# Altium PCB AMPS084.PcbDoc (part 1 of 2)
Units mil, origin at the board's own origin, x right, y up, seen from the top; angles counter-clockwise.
Board outline 7000 x 5000 mil, 4 copper layers (Top Layer, Int 2 V-, Int 3 V+, Bottom Layer), stack 61.634 mil thick; 175 components, 69 nets, 389 pads, 136 vias.
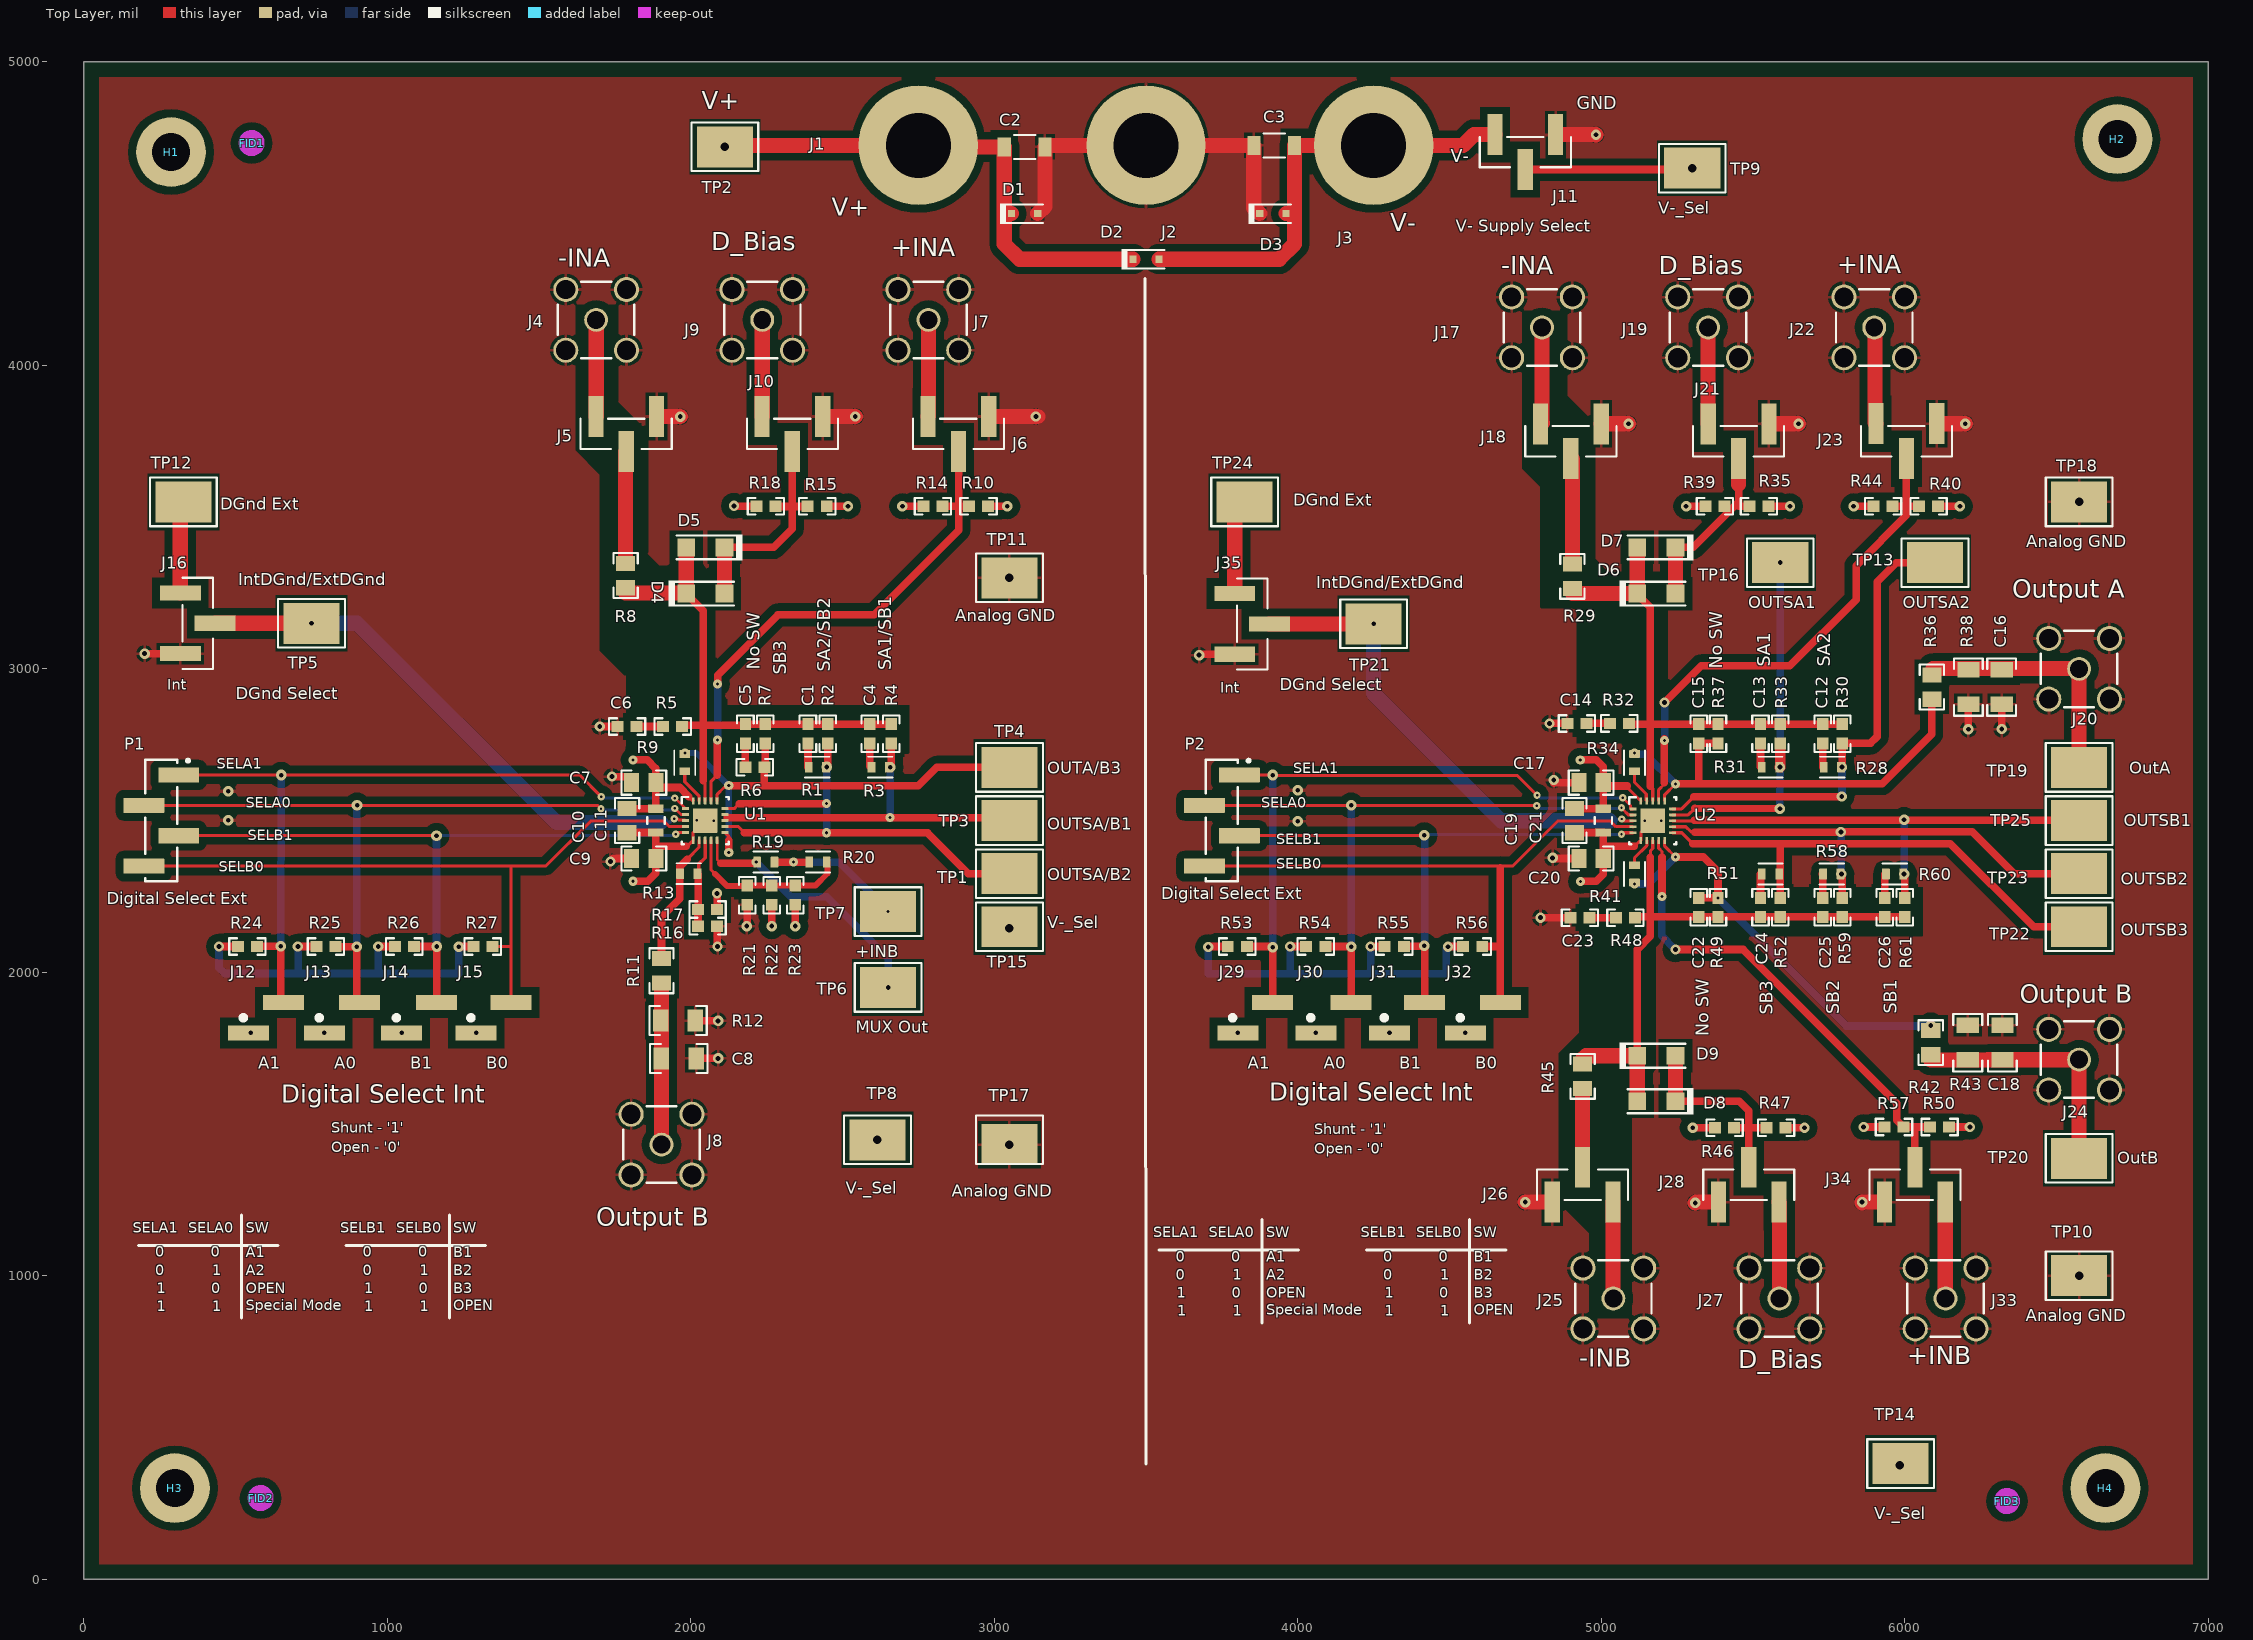
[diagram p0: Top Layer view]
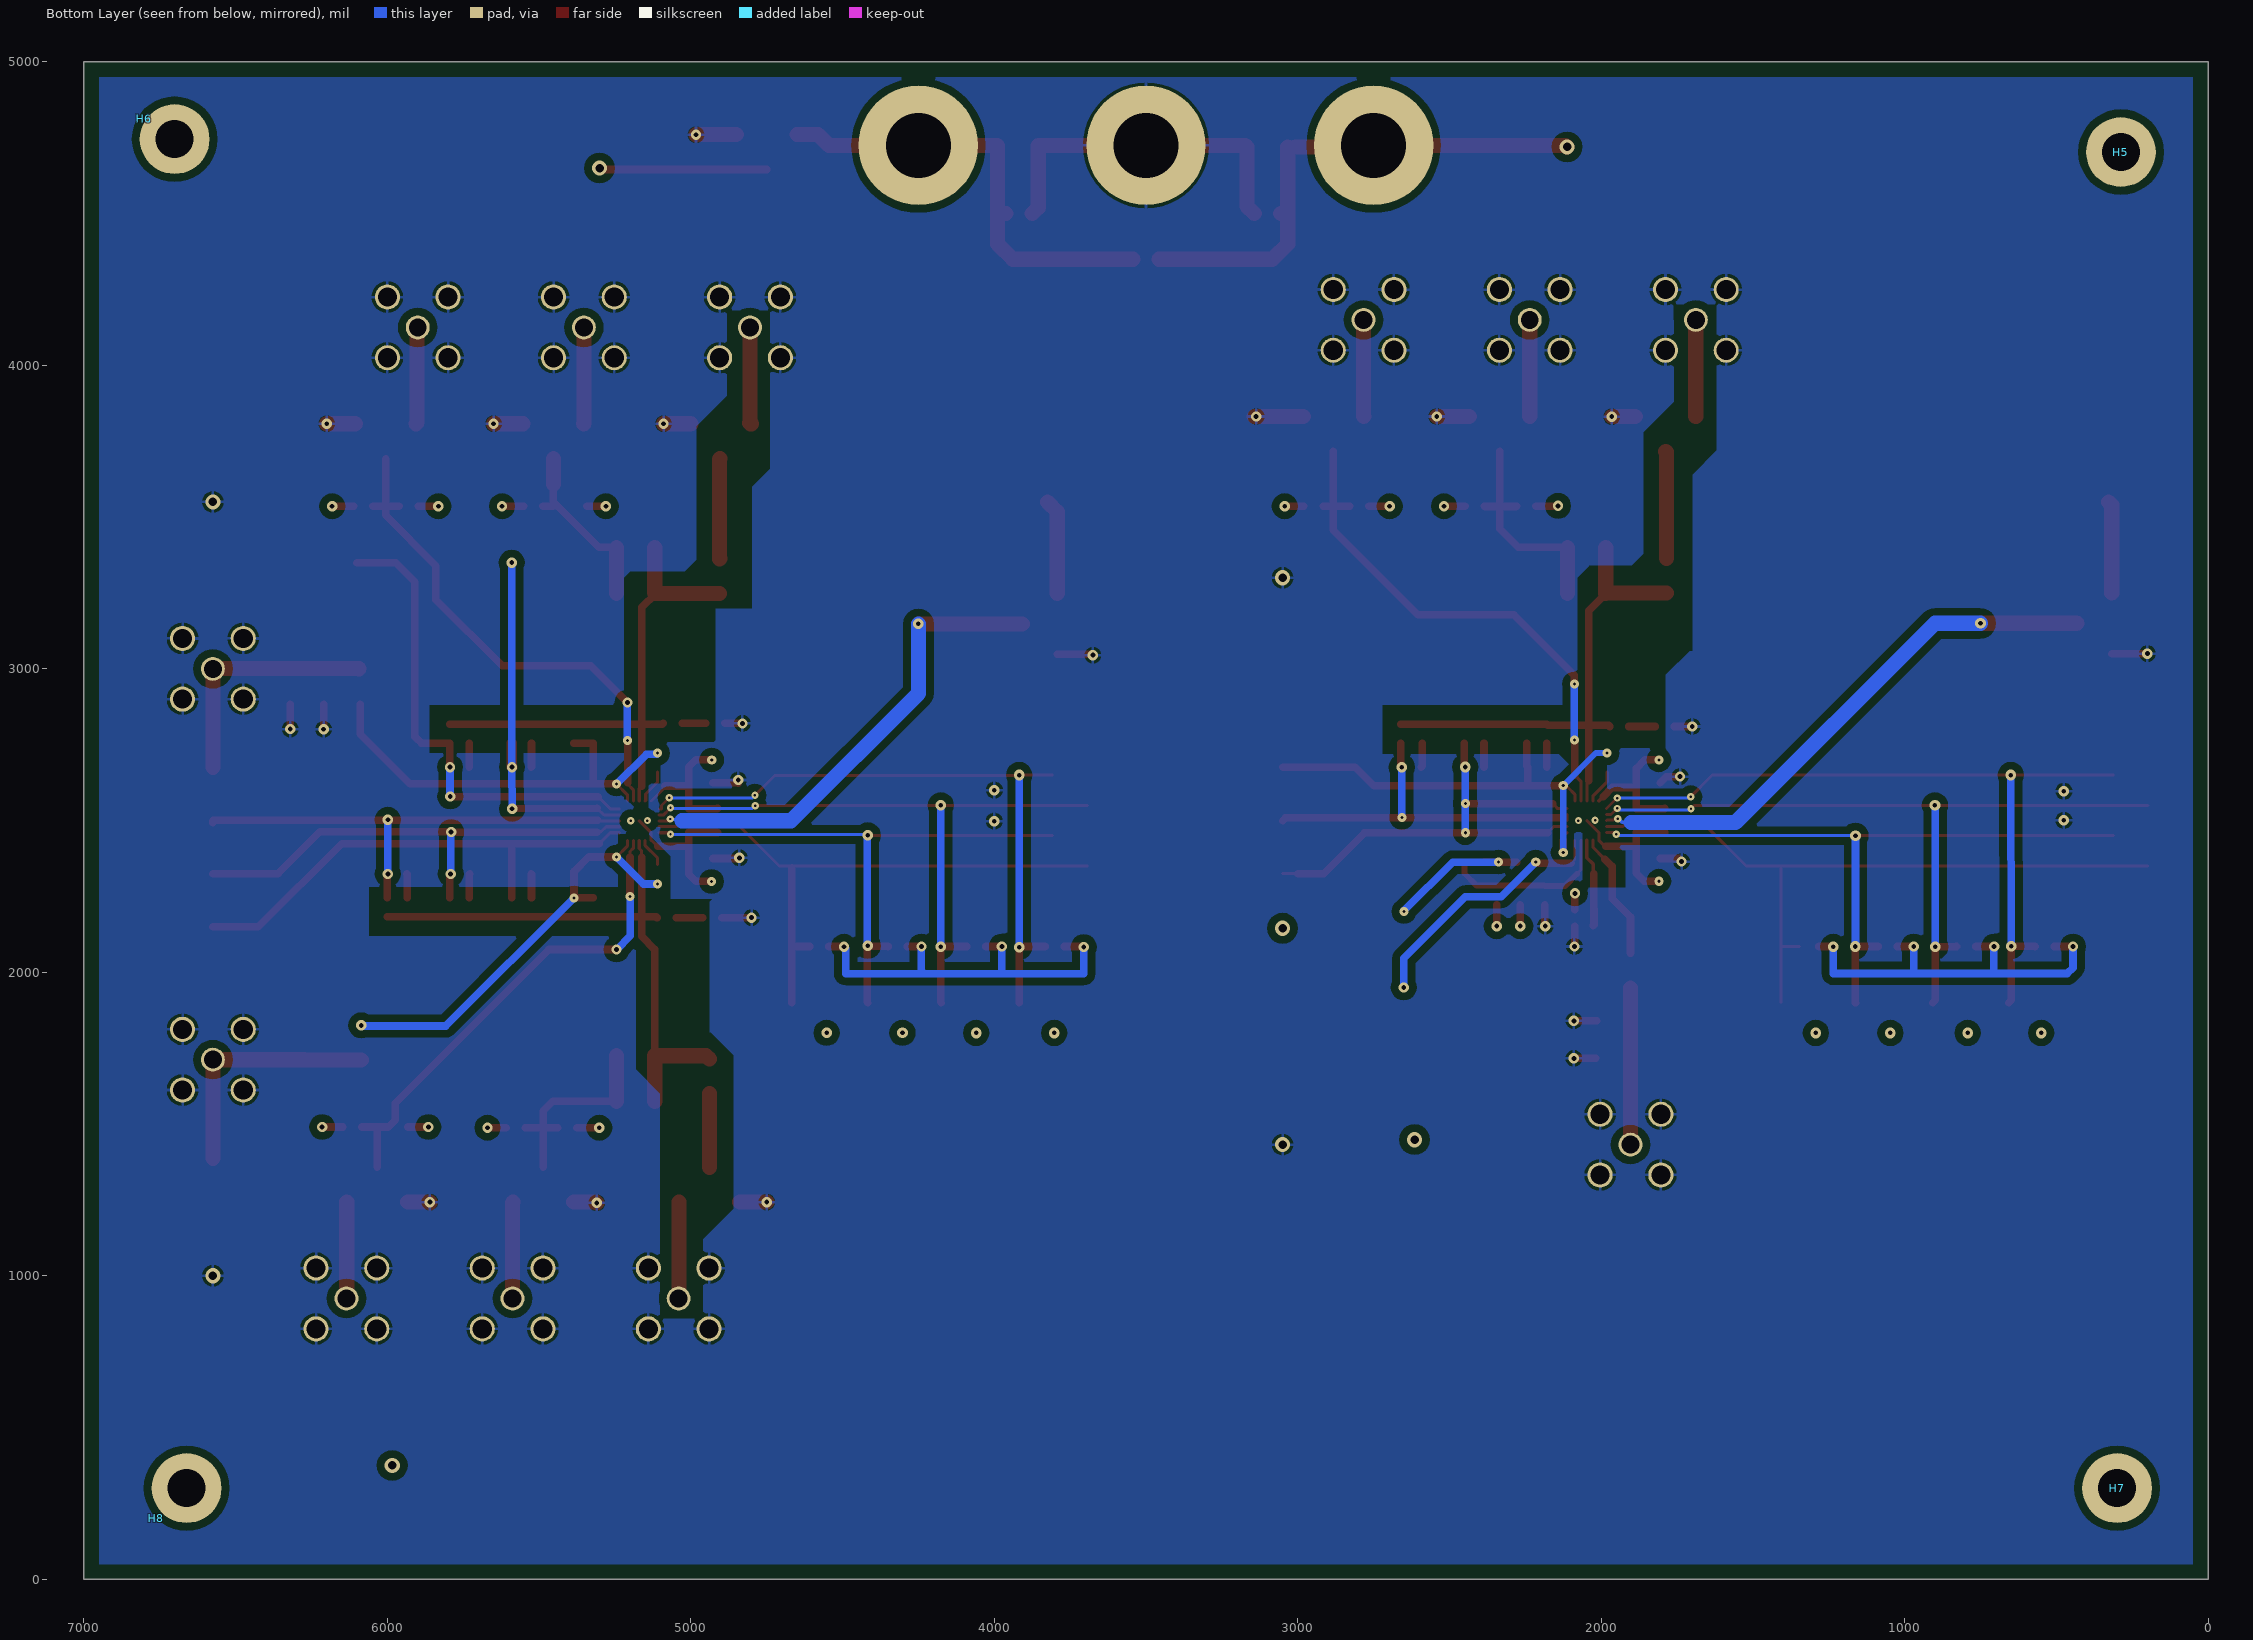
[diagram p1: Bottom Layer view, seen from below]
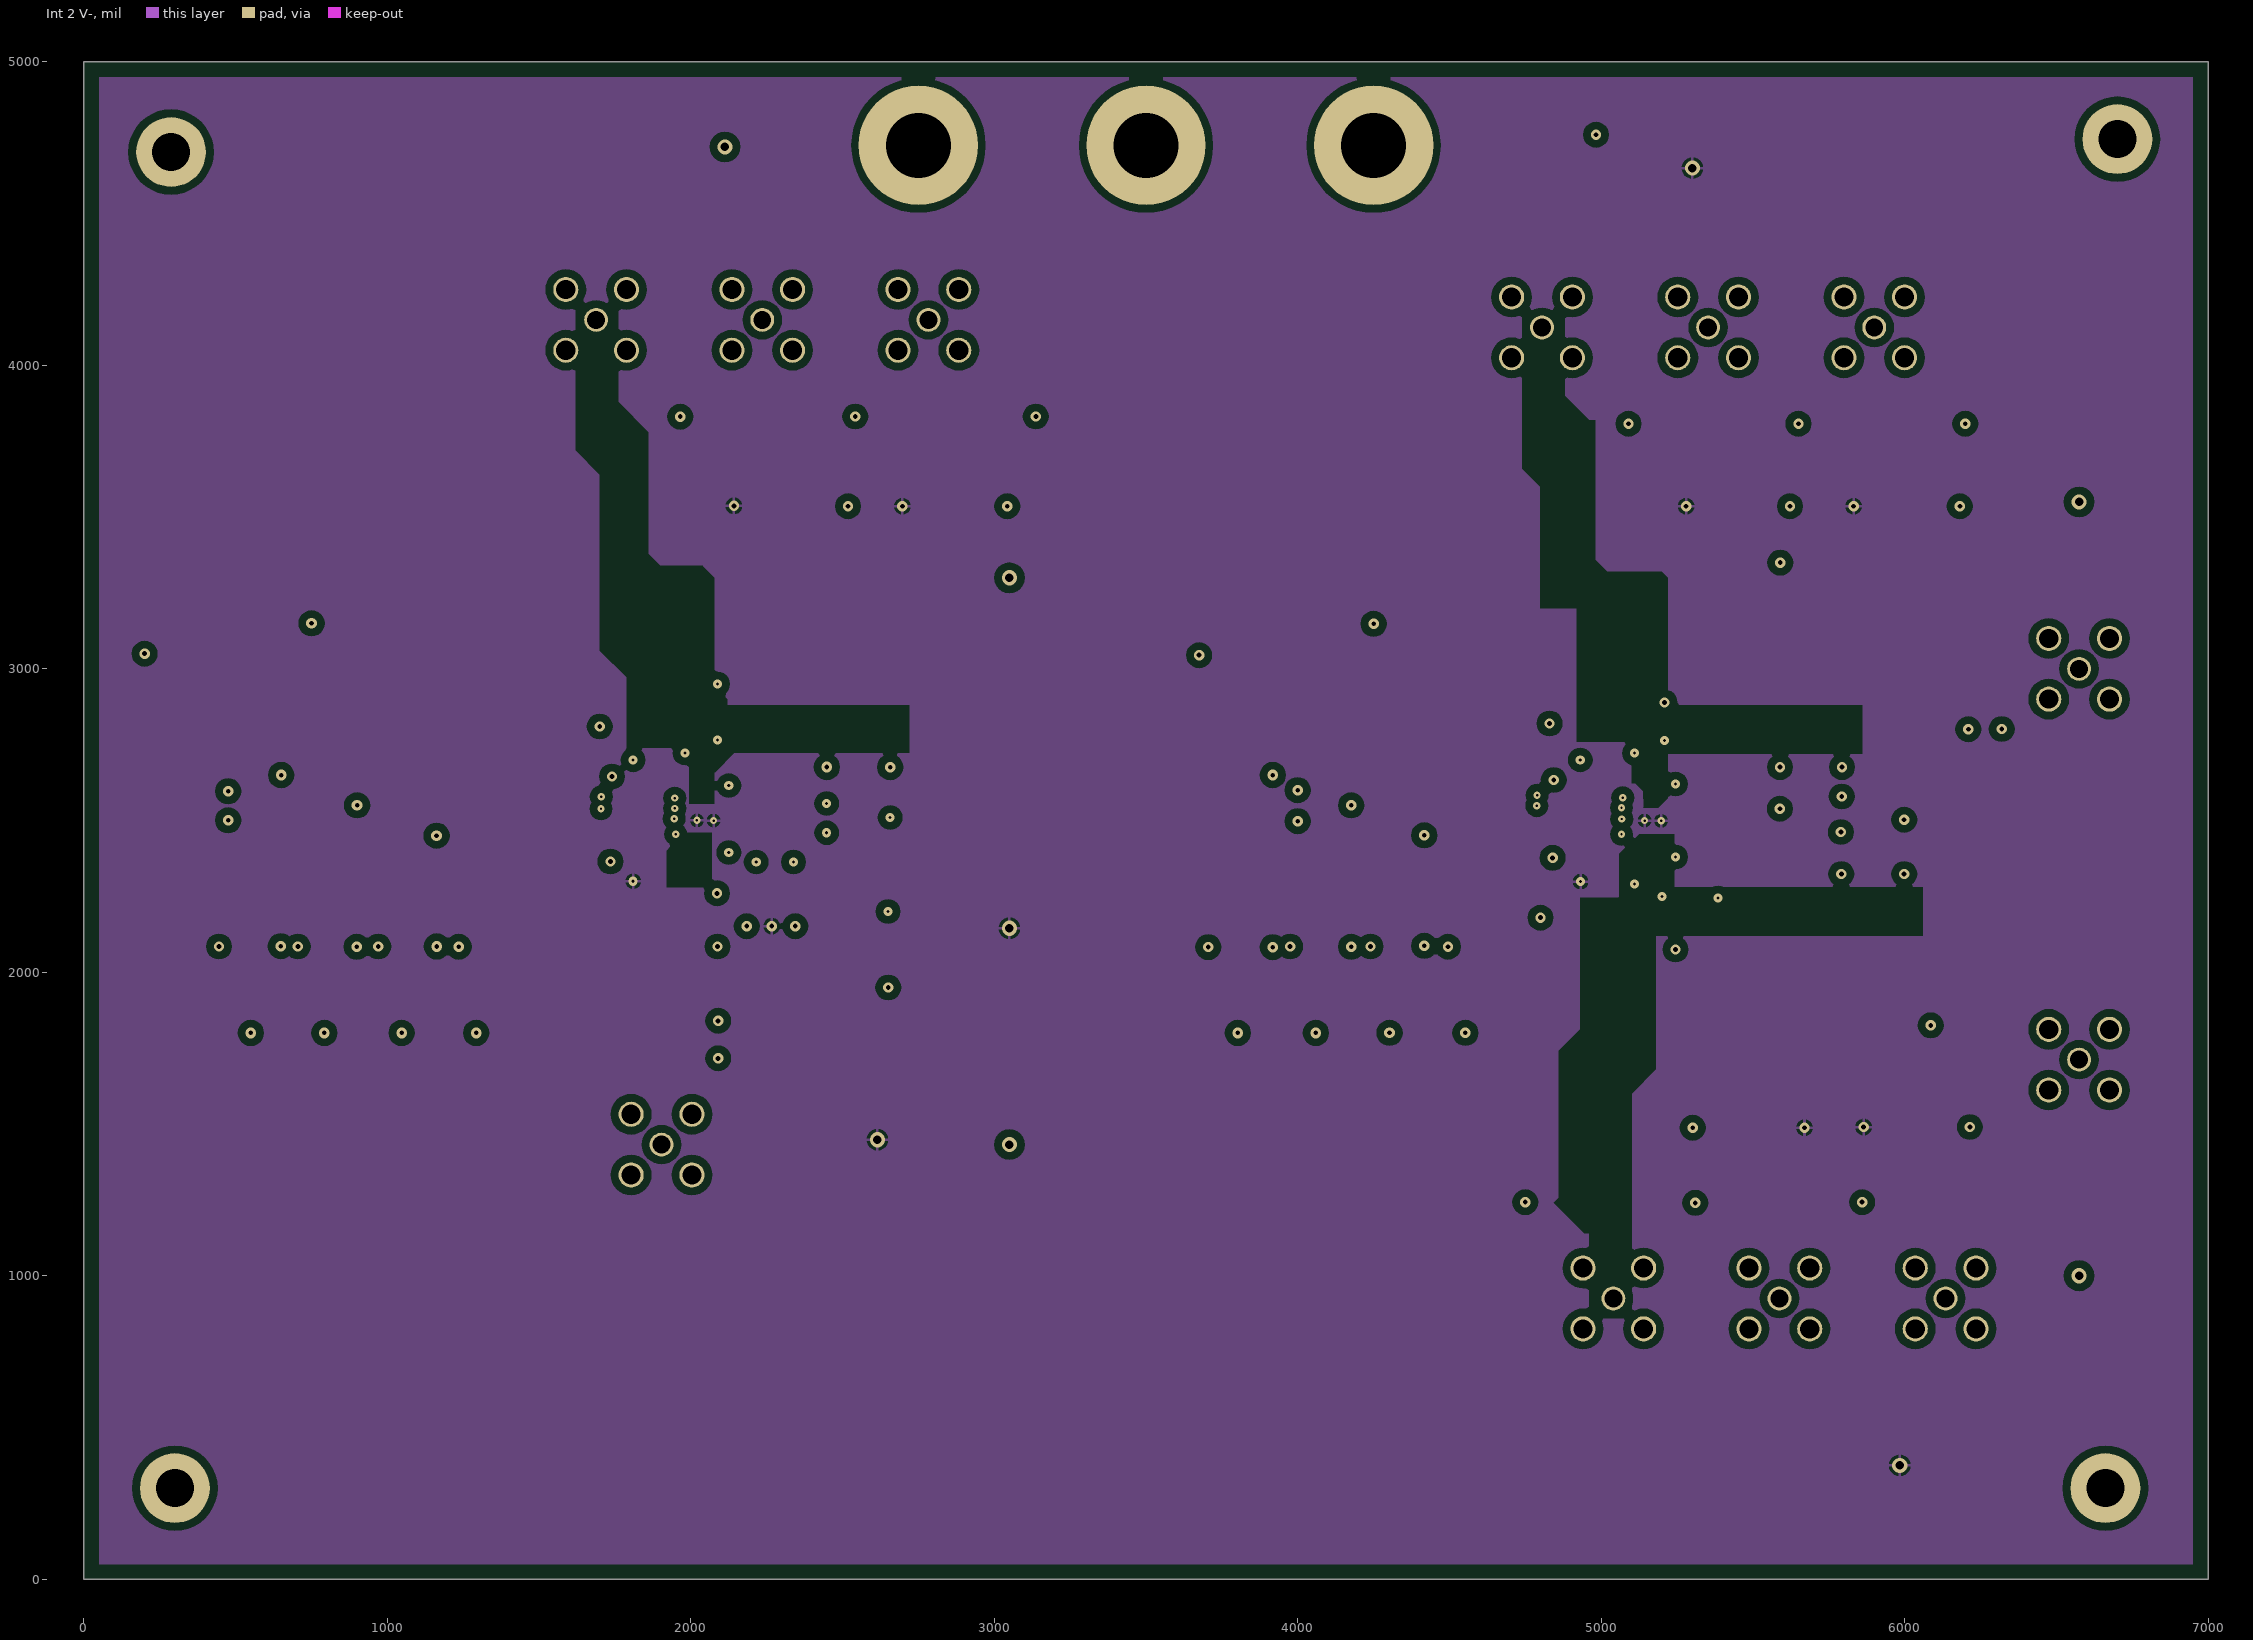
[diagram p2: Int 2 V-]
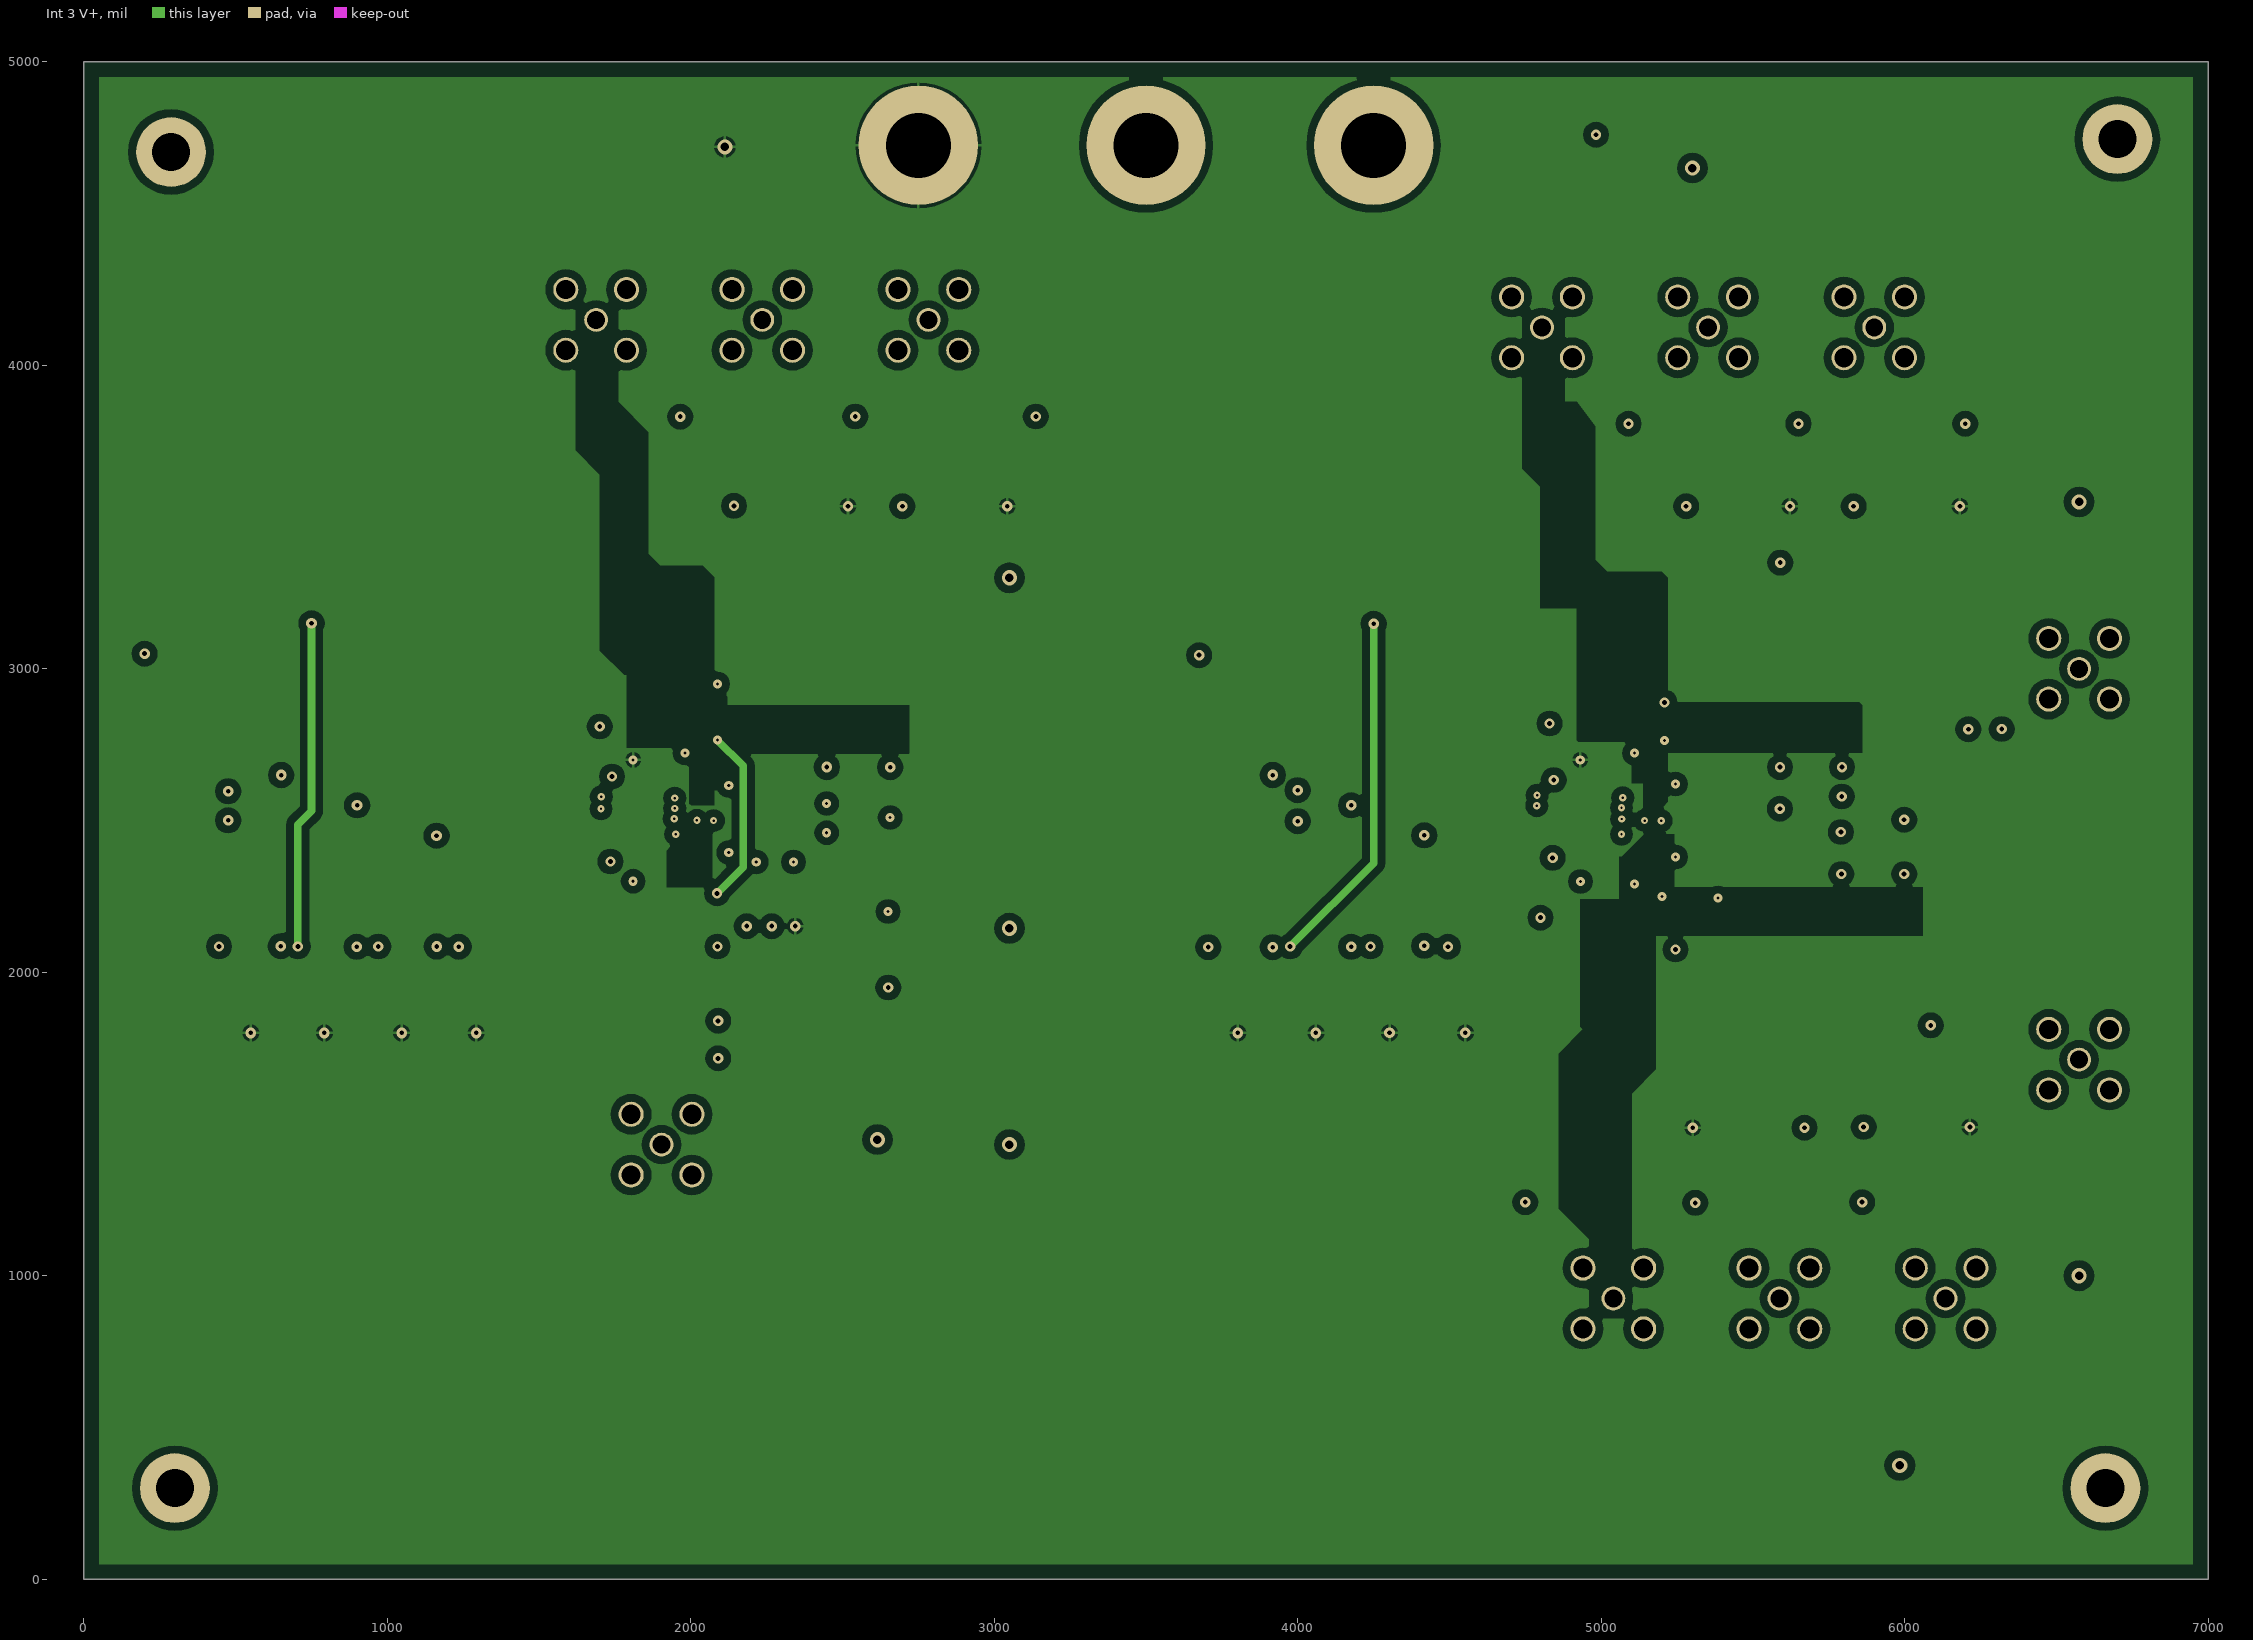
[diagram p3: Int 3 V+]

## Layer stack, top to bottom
Top Solder: solder mask 0.4, Solder Resist, Dk 3.5
Top Layer: signal copper 1.4
Dielectric 2: dielectric 10, Dk 4.2
Int 2 V-: signal copper 1.417
Dielectric1: core 36, FR-4, Dk 4.8
Int 3 V+: signal copper 1.417
Dielectric 3: dielectric 10, Dk 4.2
Bottom Layer: signal copper 1.4
Bottom Solder: solder mask 0.4, Solder Resist, Dk 3.5

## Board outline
0,0 7000,0 7000,5000 0,5000

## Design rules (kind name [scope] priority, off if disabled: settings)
AcuteAngle [All] p1: minimum=4.50000000000000E+0001 checktracksonly=FALSE
AssemblyTestPointUsage [All] p1: valid=2
BoardOutlineClearance BoardOutlineClearance_MountingHoles [OnCopper and InComponentClass('Mounting Holes')] p1: gap=39.37 ignorepadtopadclearanceinfootprint=FALSE
BoardOutlineClearance BoardOutlineClearance_Poly [OnCopper and IsPoly] p2: gap=25 ignorepadtopadclearanceinfootprint=FALSE
BoardOutlineClearance [OnCopper and Not InComponentClass('Logo') and not InComponentClass('FiducialMark') and not InRegion(1000,500,4000,800) and not InPoly] p3: gap=75 ignorepadtopadclearanceinfootprint=FALSE
Clearance Clearance_Keepouts [((IsTrack Or IsArc) And Not InPoly) And IsFree and IsKeepOut vs ((IsTrack Or IsArc) And Not InPoly) And IsFree and IsKeepOut] p1: gap=0 ignorepadtopadclearanceinfootprint=FALSE
Clearance Clearance_Poly [InPolygon] p2: gap=25 ignorepadtopadclearanceinfootprint=TRUE
Clearance Clearance_FiducialMark [IsKeepOut and InComponentClass('FiducialMark') vs IsPad and InComponentClass('FiducialMark')] p3: gap=0 ignorepadtopadclearanceinfootprint=FALSE
Clearance [All] p4: gap=7.87 ignorepadtopadclearanceinfootprint=TRUE
ComponentClearance ComponentClearance_MountingHoles_FiducialMarks [InComponentClass('Mounting Holes') vs InComponentClass('FiducialMark')] p1: gap=50 collisioncheckmode=3 verticalgap=10 showdistances=FALSE
ComponentClearance ComponentClearance_Shunt [InComponentClass('Header') vs InComponentClass('Shunt')] p2: gap=0 collisioncheckmode=3 verticalgap=0 showdistances=FALSE
ComponentClearance ComponentClearance_Logo [InComponentClass('Logo')] p3: gap=50 collisioncheckmode=3 verticalgap=10 showdistances=FALSE
ComponentClearance ComponentClearance_ScrewToNut [(HasFootprint('NY PMS 440 0025 PH')) vs (HasFootprint('Keystone_1902C'))] p4: gap=5 collisioncheckmode=3 verticalgap=10 showdistances=FALSE
ComponentClearance ComponentClearance_MountingHoles [InComponentClass('Mounting Holes')] p5: gap=250 collisioncheckmode=3 verticalgap=100000 showdistances=FALSE
ComponentClearance ComponentClearance_SmallPassives [HasFootprint('0201*') or HasFootprint('0402*') or HasFootprint('0508') or HasFootprint('0603*') or HasFootprint('0612') or HasFootprint('0805*') or HasFootprint('0815*') or HasFootprint('0830*') or HasFootprint('1206*') or HasFootprint('1210*') or HasFootprint('1808*') or HasFootprint('1812*') or HasFootprint('1825*') or HasFootprint('2010*') or HasFootprint('2220*') or HasFootprint('2225*') or HasFootprint('2512*') or HasFootprint('2728*') or HasFootprint('3518*') vs HasFootprint('0201*') or HasFootprint('0402*') or HasFootprint('0508') or HasFootprint('0603*') or HasFootprint('0612') or HasFootprint('0805*') or HasFootprint('0815*') or HasFootprint('0830*') or HasFootprint('1206*') or HasFootprint('1210*') or HasFootprint('1808*') or HasFootprint('1812*') or HasFootprint('1825*') or HasFootprint('2010*') or HasFootprint('2220*') or HasFootprint('2225*') or HasFootprint('2512*') or HasFootprint('2728*') or HasFootprint('3518*')] p6: gap=14.96 collisioncheckmode=3 verticalgap=10 showdistances=FALSE
ComponentClearance ComponentClearance_THtoSMT [IsThruComponent vs IsSMTComponent] p7: gap=40 collisioncheckmode=3 verticalgap=30 showdistances=FALSE
ComponentClearance ComponentClearance_THtoTH [IsThruComponent vs IsThruComponent] p8: gap=30 collisioncheckmode=3 verticalgap=30 showdistances=FALSE
ComponentClearance [All] p9: gap=30 collisioncheckmode=3 verticalgap=10 showdistances=FALSE
DiffPairsRouting [All] p1: maxlimit=100 minlimit=10 mostfreqgap=10 toplayer_minwidth=15 toplayer_maxwidth=15 toplayer_prefwidth=15 midlayer1_minwidth=15 midlayer1_maxwidth=15 midlayer1_prefwidth=15 midlayer2_minwidth=15 midlayer2_maxwidth=15 midlayer2_prefwidth=15 bottomlayer_minwidth=15 bottomlayer_maxwidth=15 bottomlayer_prefwidth=15 maxuncoupledlength=1000
FabricationTestPointUsage TestPointUsage [All] p1: valid=2 allowmultiple=FALSE
FabricationTestpoint Testpoint [All] p1: side=3 testpointundercomponent=TRUE minsize=40 maxsize=100 preferedsize=60 minholesize=0 maxholesize=40 preferedholesize=32 testpointgrid=1 allowsidetop=TRUE allowsidebottom=TRUE usegrid=TRUE gridtolerance=0.01
FanoutControl Fanout_LCC [IsLCC] p1: bgadir=Out bgaviamode=Centered fanoutstyle=Auto fanoutdirection=Alternating viagrid=1 // Fanout_LCC (Default Rule)
FanoutControl Fanout_BGA [IsBGA] p2: bgadir=Out bgaviamode=Centered fanoutstyle=Auto fanoutdirection=Alternating viagrid=1 // Fanout_BGA (Default Rule)
FanoutControl Fanout_Default [All] p4: bgadir=Out bgaviamode=Centered fanoutstyle=Auto fanoutdirection=Alternating viagrid=1 // Fanout_Default (Default Rule)
FanoutControl Fanout_Small [(CompPinCount < 5)] p5: bgadir=Out bgaviamode=Centered fanoutstyle=Auto fanoutdirection=OutThenIn viagrid=1 // Fanout_Small (Default Rule)
HoleSize [All] p1: absolutevalues=TRUE maxlimit=251 minlimit=7.87 maxpercent=80.000 minpercent=20.000
MinimumAnnularRing MinimumAnnularRing_ThermalPadVias [IsVia and InAnyComponent] p1: minimumring=5.91
MinimumAnnularRing [All] p2: minimumring=7.87
MinimumSolderMaskSliver MinimumSolderMaskSliver_Logo [InComponentClass('Logo') vs InComponentClass('Logo')] p1: minsoldermaskwidth=0.7
MinimumSolderMaskSliver [All] p2: minsoldermaskwidth=3.94
PlaneConnect [All] p1: planeconnectstyle=Relief reliefexpansion=10 reliefentries=4 reliefconductorwidth=10 reliefairgap=10
PolygonConnect [All] p1: connectstyle=Relief reliefconductorwidth=10 reliefentries=4 polygonreliefangle="90 Angle" airgapwidth=10
RoutingVias ThermalPadVias [IsVia and InAnyComponent] p1: holewidth=7.87 width=19.68 viastyle="Through Hole" minholewidth=7.87 minwidth=18 maxholewidth=12.99 maxwidth=23.62
RoutingVias [All] p2: holewidth=16 width=34 viastyle="Through Hole" minholewidth=7.87 minwidth=18 maxholewidth=40 maxwidth=65
SilkToBoardRegionClearance [Not ((IsComment or IsDesignator) And (Hide <> 'False')) and not InRegion(1000,500,4000,800)] p1:
SilkToSilkClearance SilkToSilkClearance_Pb-FreeLogo [(HasFootprint('Pb-Free_Overlay_Medium') OR HasFootprint('Pb-Free_Overlay_Small')) vs (HasFootprint('Pb-Free_Overlay_Medium') OR HasFootprint('Pb-Free_Overlay_Small'))] p1: silktosilkclearance=0
SilkToSilkClearance [All] p2: silktosilkclearance=3.94
SilkToSolderMaskClearance SilkToComponentPadClearance [(IsPad or IsFill or IsRegion) and InAnycomponent] p1: minsilkscreentomaskgap=5 clearancetoexposedcopper=TRUE
SilkToSolderMaskClearance "Silk to Solder Mask Opening" [All] p2: minsilkscreentomaskgap=3.94 clearancetoexposedcopper=FALSE
SolderMaskExpansion [All] p1: expansion=1.97
UnRoutedNet [All] p1: checkbadconnections=TRUE
Width [All] p1: maxlimit=100 minlimit=6 preferedwidth=10 checkconnectedcopper=TRUE
14 further rules are at their usual default settings.

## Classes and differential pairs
component class Shunt: SH-J?
component class AMPS084_schematic1: C1 C2 C3 C4 C5 C6 C7 C8 C9 C10 C11 D1 D2 D3 D4 D5 J1 J2 J3 J4 J5 J6 J7 J8 J9 J10 J11 J12 J13 J14 J15 J16 P1 R1 R2 R3 R4 R5 R6 R7 R8 R9 R10 R11 R12 R13 R14 R15 R16 R17 R18 R19 R20 R21 R22 R23 R24 R25 R26 R27 TP1 TP2 TP3 TP4 TP5 TP6 TP7 TP8 TP9 TP10 TP11 TP12 U1
component class Header: J5 J7 J10 J11 J12 J13 J14 J15 J16 J18 J21 J23 J26 J28 J29 J30 J31 J32 J34 J35
component class AMPS084_schematic2: C12 C13 C14 C15 C16 C17 C18 C19 C20 C21 C22 C23 C24 C25 C26 D6 D7 D8 D9 J17 J18 J19 J20 J21 J22 J23 J24 J25 J26 J27 J28 J29 J30 J31 J32 J33 J34 J35 P2 R28 R29 R30 R31 R32 R33 R34 R35 R36 R37 R38 R39 R40 R41 R42 R43 R44 R45 R46 R47 R48 R49 R50 R51 R52 R53 R54 R55 R56 R57 R58 R59 R60 R61 TP13 TP14 TP15 TP16 TP17 TP18 TP19 TP20 TP21 TP22 TP23 TP24 TP25 U2
component class AMPS084_Hardware: FID1 FID2 FID3 H1 H2 H3 H4 H5 H6 H7 H8 ZZ1 ZZ2 ZZ3 ZZ4
component class FiducialMark: FID1 FID2 FID3
component class AssemblyNote: ZZ1 ZZ2 ZZ3 ZZ4

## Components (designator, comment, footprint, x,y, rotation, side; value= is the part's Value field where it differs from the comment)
C1 "06035A220JAT2A" 0603 2386,2786 r90 top value=22pF
C2 "C3216X7R1E106M160AE" 1206_190 3100,4720 r180 top value=10uF
C3 "C3216X7R1E106M160AE" 1206_190 3922.26,4725 r180 top value=10uF
C4 "06035A220JAT2A" 0603 2590,2786 r90 top value=22pF
C5 "C0603C102J5GACTU" 0603 2180,2786 r90 top value=1000pF
C6 "C0603C102J5GACTU" 0603 1790,2810 r180 top value=1000pF
C7 "08055C105KAT2A" 0805_HV 1845,2625 r0 top value=1uF
C8 "C1206C104M5RACTU" 1206 1960.2,1716.3 r180 top value=0.1uF
C9 "08055C105KAT2A" 0805_HV 1845,2375 r180 top value=1uF
C10 "08055C105KAT2A" 0805_HV 1790,2500 r90 top value=1uF
C11 "GCE21BR71H104KA01L" FP-GCE21BR71H104KA01L_0805-MFG 1885,2500 r270 top
C12 "06035A220JAT2A" 0603 5730,2786 r90 top value=22pF
C13 "06035A220JAT2A" 0603 5525,2786 r90 top value=22pF
C14 "C0603C102J5GACTU" 0603 4920,2820 r180 top value=1000pF
C15 "06035A220JAT2A" 0603 5322,2786 r90 top value=22pF
C16 "C1206C104M5RACTU" 1206 6320,2940 r90 top value=0.1uF
C17 "08055C105KAT2A" 0805_HV 4967,2625 r0 top value=1uF
C18 "C1206C104M5RACTU" 1206 6322,1768.07 r270 top value=0.1uF
C19 "08055C105KAT2A" 0805_HV 4912,2500 r90 top value=1uF
C20 "08055C105KAT2A" 0805_HV 4967,2375 r180 top value=1uF
C21 "GCE21BR71H104KA01L" FP-GCE21BR71H104KA01L_0805-MFG 5007,2500 r270 top
C22 "C0603C102J5GACTU" 0603 5322,2214 r270 top value=1000pF
C23 "C0603C102J5GACTU" 0603 4930,2180 r180 top value=1000pF
C24 "06035A220JAT2A" 0603 5525,2214 r270 top value=22pF
C25 "06035A220JAT2A" 0603 5730,2214 r270 top value=22pF
C26 "06035A220JAT2A" 0603 5935,2214 r270 top value=22pF
D1 "MMSZ5233BS-7-F" SOD-323 3100,4500 r0 top value=6V
D2 "MMSZ5233BS-7-F" SOD-323 3500,4350 r0 top value=6V
D3 "MMSZ5233BS-7-F" SOD-323 3918,4500 r0 top value=6V
D4 "SFH 2701" SFH_2701 2047.79,3248.03 r0 top value=820nm
D5 "SFH 2701" SFH_2701 2048,3400 r180 top value=820nm
D6 "SFH 2701" SFH_2701 5182,3248 r0 top value=820nm
D7 "SFH 2701" SFH_2701 5182,3400 r180 top value=820nm
D8 "SFH 2701" SFH_2701 5182,1725 r0 top value=820nm
D9 "SFH 2701" SFH_2701 5182,1575 r180 top value=820nm
FID1 "Fiducial" Fiducial10-20 552.76,4732.68 r0 top
FID2 "Fiducial" Fiducial10-20 582.28,267.32 r0 top
FID3 "Fiducial" Fiducial10-20 6337.01,257.48 r0 top
H1 "PMSSS 440 0025 PH" B_F_PMSSS4400025PH 287.01,4703.15 r0 top locked
H2 "PMSSS 440 0025 PH" B_F_PMSSS4400025PH 6701.18,4745.67 r0 top locked
H3 "PMSSS 440 0025 PH" B_F_PMSSS4400025PH 300,300 r0 top locked
H4 "PMSSS 440 0025 PH" B_F_PMSSS4400025PH 6661.81,300 r0 top locked
H5 "2203" Keystone_2203 287.01,4703.15 r180 bottom locked
H6 "2203" Keystone_2203 6801.18,4812.99 r180 bottom locked
H7 "2203" Keystone_2203 300,300 r180 bottom locked
H8 "2203" Keystone_2203 6761.81,200 r180 bottom locked
J1 "V+" Keystone_575-4 2750,4725 r0 top
J2 "Analog GND" Keystone_575-4 3500,4725 r0 top
J3 "V-" Keystone_575-4 4250,4725 r180 top
J4 "-INA" TE_5-1814832-1 1688,4150 r270 top
J5 "-INA Config" Samtec_TSM-103-01-X-SV 1787,3774 r0 top
J6 "+INA" TE_5-1814832-1 2783,4150 r270 top
J7 "+INA Config" Samtec_TSM-103-01-X-SV 2882,3774 r0 top
J8 "Output B" TE_5-1814832-1 1903.41,1432 r90 top
J9 "D_Bias" TE_5-1814832-1 2235.5,4150 r0 top
J10 "D_Bias" Samtec_TSM-103-01-X-SV 2334.5,3774 r0 top
J11 "V- Supply Select" Samtec_TSM-103-01-X-SV 4750,4702.9 r0 top
J12 "A1" Samtec_TSM-102-01-L-SV 600,1850 r90 top
J13 "A0" Samtec_TSM-102-01-L-SV 850,1850 r90 top
J14 "B1" Samtec_TSM-102-01-L-SV 1104.43,1850 r90 top
J15 "B0" Samtec_TSM-102-01-L-SV 1350,1850 r90 top
J16 "DGnd Select" Samtec_TSM-103-01-X-SV 375,3150 r90 top
J17 "-INA" TE_5-1814832-1 4805,4125 r270 top
J18 "-INA Config" Samtec_TSM-103-01-X-SV 4900,3750 r0 top
J19 "D_Bias" TE_5-1814832-1 5352.5,4125 r0 top
J20 "Output A" TE_5-1814832-1 6575,3000 r180 top
J21 "D_Bias" Samtec_TSM-103-01-X-SV 5452.93,3750 r0 top
J22 "+INA" TE_5-1814832-1 5900,4125 r270 top
J23 "+INA Config" Samtec_TSM-103-01-X-SV 6005.86,3750.28 r0 top
J24 "Output B" TE_5-1814832-1 6575,1712 r180 top
J25 "-INB" TE_5-1814832-1 5040,925 r90 top
J26 "-INB Config" Samtec_TSM-103-01-X-SV 4938.96,1300 r180 top
J27 "D_Bias" TE_5-1814832-1 5587.5,925 r0 top
J28 "D_Bias" Samtec_TSM-103-01-X-SV 5486.46,1300 r180 top
J29 "A1" Samtec_TSM-102-01-L-SV 3860,1850 r90 top
J30 "A0" Samtec_TSM-102-01-L-SV 4117.48,1850.2 r90 top
J31 "B1" Samtec_TSM-102-01-L-SV 4360,1850.2 r90 top
J32 "B0" Samtec_TSM-102-01-L-SV 4610,1850.2 r90 top
J33 "+INB" TE_5-1814832-1 6135,925 r90 top
J34 "+INB Config" Samtec_TSM-103-01-X-SV 6033.96,1300 r180 top
J35 "DGnd Select" Samtec_TSM-103-01-X-SV 3850,3148.23 r90 top
P1 "Digital Select Ext" FP-TSM-104-01-L-SV-P-TR_HDR4-MFG 255,2500 r90 top
P2 "Digital Select Ext" FP-TSM-104-01-L-SV-P-TR_HDR4-MFG 3750,2500 r90 top
R1 "ERJ-3GEY0R00V" FP-ERJ-3GEY0R00V_0603-MFG 2417,2676 r0 top
R2 "RG1608P-202-B-T5" 0603 2451,2786 r270 top value=2.00k
R3 "ERJ-3GEY0R00V" FP-ERJ-3GEY0R00V_0603-MFG 2624,2676 r0 top
R4 "RG1608P-204-B-T5" 0603 2660,2786 r270 top value=200k
R5 "RG1608P-102-B-T5" 0603 1940,2810 r0 top value=1.00k
R6 "RG1608P-102-B-T5" 0603 2211,2676 r0 top value=1.00k
R7 "RG1608P-102-B-T5" 0603 2245,2786 r270 top value=1.00k
R8 "CRCW08051K00FKEA" 0805_HV 1785.08,3307.09 r270 top value=1.00k
R9 "ERJ-3GEY0R00V" FP-ERJ-3GEY0R00V_0603-MFG 1980,2691 r90 top
R10 "RCG060310K0FKEA" 0603 2948,3536 r0 top value=10.0k
R11 "CRCW0805100RFKEA" 0805_HV 1903.41,2005 r270 top value=100
R12 "CRCW120610K0FKEA" 1206 1958,1840.9 r180 top value=10.0k
R13 "ERJ-3GEY0R00V" FP-ERJ-3GEY0R00V_0603-MFG 1993.11,2325 r180 top
R14 "RCG060310K0FKEA" 0603 2798,3536 r0 top value=10.0k
R15 "RCG060310K0FKEA" 0603 2416.5,3536 r0 top value=10.0k
R16 "RT0603BRD0710KL" 0603 2055,2152 r180 top value=10.0k
R17 "RG1608P-102-B-T5" 0603 2055,2207 r180 top value=1.00k
R18 "RCG060310K0FKEA" 0603 2247.5,3536 r0 top value=10.0k
R19 "ERJ-3GEY0R00V" FP-ERJ-3GEY0R00V_0603-MFG 2247.07,2363.26 r0 top
R20 "ERJ-3GEY0R00V" FP-ERJ-3GEY0R00V_0603-MFG 2419,2363.26 r0 top
R21 "RG1608P-102-B-T5" 0603 2186.33,2254.1 r90 top value=1.00k
R22 "RG1608P-102-B-T5" 0603 2266.83,2254.1 r90 top value=1.00k
R23 "RG1608P-102-B-T5" 0603 2344,2254.1 r90 top value=1.00k
R24 "RCG060310K0FKEA" 0603 538.91,2085 r0 top value=10.0k
R25 "RCG060310K0FKEA" 0603 797.46,2085 r0 top value=10.0k
R26 "RCG060310K0FKEA" 0603 1056.01,2085 r0 top value=10.0k
R27 "RCG060310K0FKEA" 0603 1314.57,2085 r0 top value=10.0k
R28 "ERJ-3GEY0R00V" FP-ERJ-3GEY0R00V_0603-MFG 5762,2676 r0 top
R29 "CRCW08051K00FKEA" 0805_HV 4905,3305 r270 top value=1.00k
R30 "RG1608P-202-B-T5" 0603 5795,2786 r270 top value=2.00k
R31 "ERJ-3GEY0R00V" FP-ERJ-3GEY0R00V_0603-MFG 5558,2676 r0 top
R32 "RG1608P-102-B-T5" 0603 5060,2820 r0 top value=1.00k
R33 "RG1608P-203-B-T5" 0603 5590,2786 r270 top value=20.0k
R34 "ERJ-3GEY0R00V" FP-ERJ-3GEY0R00V_0603-MFG 5110,2691 r90 top
R35 "RCG060310K0FKEA" 0603 5520,3536 r0 top value=10.0k
R36 "CRCW0805100RFKEA" 0805_HV 6090,2940 r90 top value=100
R37 "RG1608P-204-B-T5" 0603 5385,2786 r270 top value=200k
R38 "CRCW120610K0FKEA" 1206 6210,2940 r90 top value=10.0k
R39 "RCG060310K0FKEA" 0603 5375,3536 r0 top value=10.0k
R40 "RCG060310K0FKEA" 0603 6079,3536 r0 top value=10.0k
R41 "ERJ-3GEY0R00V" FP-ERJ-3GEY0R00V_0603-MFG 5110,2324.03 r270 top
R42 "CRCW0805100RFKEA" 0805_HV 6086,1768.07 r270 top value=100
R43 "CRCW120610K0FKEA" 1206 6208.03,1768.07 r270 top value=10.0k
R44 "RCG060310K0FKEA" 0603 5929,3536 r0 top value=10.0k
R45 "CRCW08051K00FKEA" 0805_HV 4938.96,1657.2 r90 top value=1.00k
R46 "RCG060310K0FKEA" 0603 5406.5,1487.74 r180 top value=10.0k
R47 "RCG060310K0FKEA" 0603 5576.46,1487.74 r180 top value=10.0k
R48 "RG1608P-102-B-T5" 0603 5080,2180 r0 top value=1.00k
R49 "RG1608P-102-B-T5" 0603 5385,2214 r90 top value=1.00k
R50 "RCG060310K0FKEA" 0603 6115,1490 r0 top value=10.0k
R51 "ERJ-3GEY0R00V" FP-ERJ-3GEY0R00V_0603-MFG 5558,2324 r0 top
R52 "RG1608P-202-B-T5" 0603 5590,2214 r90 top value=2.00k
R53 "RCG060310K0FKEA" 0603 3800.9,2085 r0 top value=10.0k
R54 "RCG060310K0FKEA" 0603 4059.46,2085 r0 top value=10.0k
R55 "RCG060310K0FKEA" 0603 4318.01,2085 r0 top value=10.0k
R56 "RCG060310K0FKEA" 0603 4576.57,2085 r0 top value=10.0k
R57 "RCG060310K0FKEA" 0603 5965,1490 r0 top value=10.0k
R58 "ERJ-3GEY0R00V" FP-ERJ-3GEY0R00V_0603-MFG 5760,2324 r0 top
R59 "RG1608P-203-B-T5" 0603 5795,2214 r90 top value=20.0k
R60 "ERJ-3GEY0R00V" FP-ERJ-3GEY0R00V_0603-MFG 5967,2324 r0 top
R61 "RG1608P-204-B-T5" 0603 6000,2214 r90 top value=200k
TP1 "OUTSA/B2" Testpoint_Keystone_Compact#1 3050,2325 r0 top
TP2 "V+" Testpoint_Keystone_Compact#1 2112.2,4720 r0 top
TP3 "OUTSA/B1" Testpoint_Keystone_Compact#1 3050,2500 r0 top
TP4 "OUTA/B3" Testpoint_Keystone_Compact#1 3050,2675 r0 top
TP5 "IntDGnd/ExtDGnd" Testpoint_Keystone_Compact#1 750,3150 r0 top
TP6 "MUX Out" Testpoint_Keystone_Compact#1 2650,1950 r0 top
TP7 "+INB" Testpoint_Keystone_Compact#1 2650,2200 r0 top
TP8 "V-_Sel" Testpoint_Keystone_Compact#1 2615,1448 r0 top
TP9 "V-_Sel" Testpoint_Keystone_Compact#1 5300,4650 r180 top
TP10 "Analog GND" Testpoint_Keystone_Compact#1 6575,1000 r0 top
TP11 "Analog GND" Testpoint_Keystone_Compact#1 3050,3300 r0 top
TP12 "DGnd Ext" Testpoint_Keystone_Compact#1 327.76,3550 r0 top
TP13 "OUTSA2" Testpoint_Keystone_Compact#1 6100,3350 r0 top
TP14 "V-_Sel" Testpoint_Keystone_Compact#1 5987,381 r0 top
TP15 "V-_Sel" Testpoint_Keystone_Compact#1 3050,2150 r0 top
TP16 "OUTSA1" Testpoint_Keystone_Compact#1 5590,3350 r0 top
TP17 "Analog GND" Testpoint_Keystone_Compact#2 3050,1448 r0 top
TP18 "Analog GND" Testpoint_Keystone_Compact#1 6575,3550 r0 top
TP19 "OutA" Testpoint_Keystone_Compact#1 6575,2675 r0 top
TP20 "OutB" Testpoint_Keystone_Compact#1 6575,1387 r0 top
TP21 "IntDGnd/ExtDGnd" Testpoint_Keystone_Compact#1 4250,3148.23 r0 top
TP22 "OUTSB3" Testpoint_Keystone_Compact#1 6575,2150 r0 top
TP23 "OUTSB2" Testpoint_Keystone_Compact#1 6575,2325 r0 top
TP24 "DGnd Ext" Testpoint_Keystone_Compact#1 3825,3550 r0 top
TP25 "OUTSB1" Testpoint_Keystone_Compact#1 6575,2500 r0 top
U1 "OPA3S328RGR" RGR0020A 2047.24,2500 r0 top
U2 "OPA3S328RGR" RGR0020A 5170,2499.21 r0 top
ZZ1 "This Assembly Note is for PCB labels only" AssemblyNoteLabel 177.17,6131.89 r0 top
ZZ2 "These assemblies are ESD sensitive, ESD precautions shall be observed." AssemblyNote 167.32,6003.94 r0 top
ZZ3 "These assemblies must be clean and free from flux and all contaminants. Use of no clean flux is not acceptable." AssemblyNote 167.32,5866.14 r0 top
ZZ4 "These assemblies must comply with workmanship standards IPC-A-610 Class 2, unless otherwise specified." AssemblyNote 167.32,5728.35 r0 top

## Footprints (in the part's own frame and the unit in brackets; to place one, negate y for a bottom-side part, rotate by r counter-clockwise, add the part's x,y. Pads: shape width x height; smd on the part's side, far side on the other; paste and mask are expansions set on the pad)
0603 [mm] "0603 from SM-752 data"
  rect 1x0.95 smd: 1(-0.8,0) 2(0.8,0)
  silkscreen extent -1.52,-0.69 1.52,0.69, body extent -0.87,-0.47 0.87,0.47, height 1
0805_HV [mil] "0805 with 30mil clearance between pads"
  rect 50x63 smd: 1(-40,0) 2(40,0)
  silkscreen extent -74,-40 74,40, body extent -43,-29 43,29, height 57
1206 [mm] "1206 from SM-752 data"
  rect 1.3x1.85 smd: 1(-1.45,0) 2(1.45,0)
  silkscreen extent -2.4,-1.21 2.4,1.21, body extent -1.7,-0.9 1.7,0.9, height 1.35
1206_190 [mm] "1206_190"
  rect 1.1x1.6 smd: 1(-1.7,0) 2(1.7,0)
  silkscreen extent -0.9,-1 0.9,1, body extent -1.75,-0.95 1.75,0.95, height 1.9
AssemblyNote [mil] "Assembly Note"
AssemblyNoteLabel [mil] "Assembly Note for PCB Labels"
B_F_PMSSS4400025PH [mil] "MACHINE SCREW PAN PHILLIPS 4-40"
  round 230 hole 125: 1(0,0)
  body extent -109,-109 110,110, height 79
Fiducial10-20 [mm]
  round 1 smd mask+0.5: 1(0,0)
  Top Layer keep-out circle w1.178: c0,0 r0.5
FP-ERJ-3GEY0R00V_0603-MFG [mm]
  rrect15% 0.65x0.9 smd paste+0 mask+0: 1(-0.725,0) 2(0.725,0)
  silkscreen extent -1.03,-0.87 1.03,0.87, body extent -1.15,-0.58 1.15,0.58, height 0.25
FP-GCE21BR71H104KA01L_0805-MFG [mm]
  rrect14% 0.7x1.3 smd paste+0 mask+0: 1(-1,0) 2(1,0)
  silkscreen extent -0.28,-0.72 0.28,0.72, body extent -1.45,-0.82 1.45,0.82, height 0.25
FP-TSM-104-01-L-SV-P-TR_HDR4-MFG [mil]
  rrect8% 50x135 smd paste+0 mask+0: 1(150,-57.5) 2(50,57.5) 3(-50,-57.5) 4(-150,57.5)
  silkscreen extent -200,-93 202,53, body extent -204,-129 204,129, height 10
Keystone_575-4 [mm] "Banana Jack"
  round 10 hole 5.45: 1(0,0)
  body extent -3.95,-3.95 3.92,3.93, height 2.36
Keystone_2203 [mil] "HEX STANDOFF 4-40 ALUMINUM 1/2\""
  body extent -144,-125 144,125, height 495
RGR0020A [mm] "QFN, 20-Leads, Body 3.5x3.5mm, Pitch 0.5mm, Thermal Pad 2.05x2.05mm, TI Recommended"
  rrect42% 0.6x0.24 smd: 1(-1.65,1) 2(-1.65,0.5) 3(-1.65,0) 4(-1.65,-0.5) 5(-1.65,-1) 11(1.65,-1) 12(1.65,-0.5) 13(1.65,0) 14(1.65,0.5) 15(1.65,1)
  rrect42% 0.24x0.6 smd: 6(-1,-1.65) 7(-0.5,-1.65) 8(0,-1.65) 9(0.5,-1.65) 10(1,-1.65) 16(1,1.65) 17(0.5,1.65) 18(0,1.65) 19(-0.5,1.65) 20(-1,1.65)
  rrect5% 2.05x2.05 smd paste-1.025: 21(0,0)
  silkscreen extent -1.97,-1.97 1.97,1.97, body extent -1.75,-1.75 1.75,1.75, height 1
Samtec_TSM-102-01-L-SV [mm] "SAMTEC"
  rect 1.27x3.43 smd: 1(-1.27,1.46) 2(1.27,-1.46)
  silkscreen extent -0.2,1.7 0.2,2.1, body extent -2.53,-2.45 2.55,2.45, height 9.65
Samtec_TSM-103-01-X-SV [mil] "Samtec recommended land pattern"
  rect 50x135 smd: 1(-100,57.5) 2(0,-57.5) 3(100,57.5)
  silkscreen extent -150,-50 150,50, body extent -150,-104 150,104, height 381
SFH_2701 [mm] "SMD, 2-Leads, Body 3.2x1.5mm"
  rect 1.5x1.5 smd paste-0.05 mask+0.05: 1(-1.6,0) 2(1.6,0)
  silkscreen extent -3.1,-1.1 2.4,1.1, body extent -1.68,-0.83 1.68,0.83, height 1.25
SOD-323 [mm] "NXP recommended land pattern"
  rect 0.6x0.6 smd paste-0.05: 1(-1.1,0) 2(1.1,0)
  silkscreen extent -2.06,-0.86 1.53,0.86, body extent -1.3,-0.67 1.3,0.68, height 1.1
TE_5-1814832-1 [mm] "SMA Straight PCB Socket Die Cast, TH"
  round 2 hole 1.5: 1(0,0)
  round 2.1 hole 1.6: 2(-2.54,2.54) 3(-2.54,-2.54) 4(2.54,-2.54) 5(2.54,2.54)
  silkscreen extent -3.2,-3.2 3.2,3.2, body extent -3.2,-3.2 3.2,3.2, height 9.5
Testpoint_Keystone_Compact#1 [mil] "Compact SMT test point"
  rect 185x135 smd: 1(0,0)
  silkscreen extent -110,-80 110,80, body extent -75,-56 75,56, height 91
Testpoint_Keystone_Compact#2 [mil] "Compact SMT test point"
  rect 185x135 smd: 1(0,-16)
  silkscreen extent -110,-80 110,80, body extent -75,-56 75,56, height 91

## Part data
C1 C4 C12 C13 C15 C24 C25 C26: library part CMP-0006775-4, "CAP, CERM, 22 pF, 50 V, +/- 5%, C0G/NP0, 0603", Cap_Case=0603, Manufacturer=AVX, Supplier Part Number 1=478-1167-1-ND, TempCo=C0G/NP0, Tolerance_%=5%, Value1="0.259 ohm", Value2=50V, ValueDisplayed=22pF
C2 C3: library part CMP-0008692-1, "CAP, CERM, 10 uF, 25 V, +/- 20%, X7R, 1206_190", Cap_Case=1206, Manufacturer=TDK, Supplier Part Number 1=445-6812-1-ND, TempCo=X7R, Tolerance_%=20%, Value1=Unknown, Value2=25V, ValueDisplayed=10uF
C5 C6 C14 C22 C23: library part CMP-0006843-4, "CAP, CERM, 1000 pF, 50 V, +/- 5%, C0G/NP0, 0603", Cap_Case=0603, Manufacturer=Kemet, Supplier Part Number 1=399-3293-1-ND, TempCo=C0G/NP0, Tolerance_%=5%, Value1=Unknown, Value2=50V, ValueDisplayed=1000pF
C7 C9 C10 C17 C19 C20: library part CMP-0007634-2, "CAP, CERM, 1 uF, 50 V, +/- 10%, X7R, 0805", Cap_Case=0805, Manufacturer=AVX, Supplier Part Number 1=478-7956-1-ND, TempCo=X7R, Tolerance_%=10%, Value1=Unknown, Value2=50V, ValueDisplayed=1uF
C8 C16 C18: library part CMP-0008587-2, "CAP, CERM, 0.1 uF, 50 V, +/- 20%, X7R, 1206", Cap_Case=1206, Manufacturer=Kemet, Supplier Part Number 1=399-1248-1-ND, TempCo=X7R, Tolerance_%=20%, Value1="0.059 ohm", Value2=50V, ValueDisplayed=0.1uF
C11 C21: library part CMP-0088731-1, "0.1µF ±10% 50V Ceramic Capacitor X7R 0805 (2012 Metric)", Digikey Part Number=490-16485-1-ND, Manufacturer=Murata, Mouser Part Number=81-GCE21BR71H104KA1L, Operating Temperature Range="-55°C to +125°C", TempCo=15%, Temperature Characteristic=X7R, Tolerance_%=10%, ValueDisplayed=0.1uF
D1 D2 D3: library part CMP-0005856-3, "Diode, Zener, 6 V, 200 mW, SOD-323", Manufacturer="Diodes Inc.", Power_W=200mW, Value1=0.2W
D4 D5 D6 D7 D8 D9: library part CMP-0002013-4, "High Speed PIN Photodiode, SMD", Manufacturer=OSRAM
FID1 FID2 FID3: library part CMP-0077181-1, "Fiducial mark.  There is nothing to buy or mount.", Manufacturer=N/A
H1 H2 H3 H4: library part CMP-0003715-1, "MACHINE SCREW PAN PHILLIPS 4-40", Manufacturer="B&F Fastener Supply", Supplier Part Number 1=H703-ND
H5 H6 H7 H8: library part CMP-0003779-1, Manufacturer=Keystone, Supplier Part Number 1=36-2203-ND
J1 J2 J3: library part CMP-0055165-1, "Standard Banana Jack, Uninsulated, 5.5mm", Manufacturer=Keystone, PartNumber=575-4, Supplier Part Number 1=36-575-4-ND
J4 J6 J8 J9 J17 J19 J20 J22 J24 J25 J27 J33: library part CMP-0054990-1, "SMA Straight PCB Socket Die Cast, 50 Ohm, TH", Manufacturer="TE Connectivity", PartNumber=5-1814832-1, Supplier Part Number 1=A97594-ND
J5 J7 J10 J11 J16 J18 J21 J23 J26 J28 J34 J35: library part CMP-0075402-1, "Header, 100mil, 3x1, Gold, SMT", Manufacturer=Samtec, PartNumber=TSM-103-01-L-SV, Supplier Part Number 1=TSM-103-01-L-SV-ND
J12 J13 J14 J15 J29 J30 J31 J32: library part CMP-0075467-1, "Header, 100mil, 2x1, Gold with Tin Tail, SMT", Color=Black, Current_A=5.4A, Manufacturer=Samtec, PartNumber=TSM-102-01-L-SV, Supplier Part Number 1=TSM-102-01-L-SV-ND, Voltage_V=475V
P1 P2: library part CMP-0087359-1, Current_A=5.4A, Manufacturer=Samtec, PartNumber=TSM-104-01-L-SV-P-TR, Voltage_V=475V
R1 R3 R9 R13 R19 R20 R28 R31 R34 R41 R51 R58 R60: library part CMP-0089143-1, "0 Ohms Jumper 0.1W, 1/10W Chip Resistor 0603 (1608 Metric) Automotive AEC-Q200 Thick Film", Digikey Part Number=P0.0GCT-ND, Manufacturer=Panasonic, Mouser Part Number=667-ERJ-3GEY0R00V, Operating Temperature Range="-55°C to +155°C", Power_W=100mW, TempCo=-100/+600ppm/°C, Tolerance_%=5%
R2 R30 R52: library part CMP-0023463-3, "RES, 2.00 k, 0.1%, 0.1 W, 0603", Manufacturer="Susumu Co Ltd", Power_W=100mW, Supplier Part Number 1=RG16P2.0KBCT-ND, TempCo="25 ppm/C", Tolerance_%=0.1%, Value2=0.1W, Value_Code=2k00, ValueDisplayed=2.00k
R4 R37 R61: library part CMP-0023465-3, "RES, 200 k, 0.1%, 0.1 W, 0603", Manufacturer="Susumu Co Ltd", Power_W=100mW, Supplier Part Number 1=RG16P200KBCT-ND, TempCo="25 ppm/C", Tolerance_%=0.1%, Value2=0.1W, Value_Code=200k
R5 R6 R7 R17 R21 R22 R23 R32 R48 R49: library part CMP-0023403-3, "RES, 1.00 k, 0.1%, 0.1 W, 0603", Manufacturer="Susumu Co Ltd", Power_W=100mW, Supplier Part Number 1=RG16P1.0KBCT-ND, TempCo="25 ppm/C", Tolerance_%=0.1%, Value2=0.1W, Value_Code=1k00, ValueDisplayed=1.00k
R8 R29 R45: library part CMP-0020951-3, "RES, 1.00 k, 1%, 0.125 W, AEC-Q200 Grade 0, 0805", Manufacturer=Vishay-Dale, Power_W=125mW, Supplier Part Number 1=541-1.00KCCT-ND, TempCo="100 ppm/C", Tolerance_%=1%, Value2=0.125W, Value_Code=1k00, ValueDisplayed=1.00k
R10 R14 R15 R18 R24 R25 R26 R27 R35 R39 R40 R44 R46 R47 R50 R53 R54 R55 R56 R57: library part CMP-0023337-3, "RES, 10.0 k, 1%, 0.1 W, 0603", Manufacturer="Vishay Draloric", Power_W=100mW, Supplier Part Number 1=541-1784-1-ND, TempCo="100 ppm/C", Tolerance_%=1%, Value2=0.1W, Value_Code=10k0, ValueDisplayed=10.0k
R11 R36 R42: library part CMP-0020835-3, "RES, 100, 1%, 0.125 W, AEC-Q200 Grade 0, 0805", Manufacturer=Vishay-Dale, Power_W=125mW, Supplier Part Number 1=541-100CCT-ND, TempCo="100 ppm/C", Tolerance_%=1%, Value2=0.125W, Value_Code=100R, ValueDisplayed=100
R12 R38 R43: library part CMP-0016577-1, "RES, 10.0 k, 1%, 0.25 W, 1206", Manufacturer=Vishay-Dale, Power_W=250mW, Supplier Part Number 1=541-10.0KFCT-ND, TempCo="100 ppm/C", Tolerance_%=1%, Value2=0.25W, Value_Code=10k0, ValueDisplayed=10.0k
R16: library part CMP-0023653-3, "RES, 10.0 k, 0.1%, 0.1 W, 0603", Manufacturer="Yageo America", Power_W=100mW, TempCo="25 ppm/C", Tolerance_%=0.1%, Value2=0.1W, Value_Code=10k0, ValueDisplayed=10.0k
R33 R59: library part CMP-0023464-3, "RES, 20.0 k, 0.1%, 0.1 W, 0603", Manufacturer="Susumu Co Ltd", Power_W=100mW, Supplier Part Number 1=RG16P20.0KBCT-ND, TempCo="25 ppm/C", Tolerance_%=0.1%, Value2=0.1W, Value_Code=20k0, ValueDisplayed=20.0k
TP1 TP2 TP3 TP4 TP5 TP6 TP7 TP8 TP9 TP10 TP11 TP12 TP13 TP14 TP15 TP16 TP17 TP18 TP19 TP20 TP21 TP22 TP23 TP24 TP25: library part CMP-0055153-1, "Test Point, Compact, SMT", Manufacturer=Keystone, PartNumber=5016, Supplier Part Number 1=36-5016TR-ND
U1 U2: library part CMP-0860039-1, "40-MHz CMOS Operational Amplifier With Switches, RGR0020A (VQFN-20)", Alternate Manufacturer="Texas Instruments"
ZZ1: library part CMP-0003616-3
ZZ2: library part CMP-0077236-1
ZZ3: library part CMP-0077237-1
ZZ4: library part CMP-0077238-1

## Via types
v1: diameter 34, hole 16, Top Layer to Bottom Layer, 61 vias
v2: diameter 35, hole 15, Top Layer to Bottom Layer, 28 vias
v3: diameter 30, hole 10, Top Layer to Bottom Layer, 22 vias
v4: diameter 24, hole 8, Top Layer to Bottom Layer, 16 vias
v5: diameter 50, hole 28, Top Layer to Bottom Layer, 9 vias

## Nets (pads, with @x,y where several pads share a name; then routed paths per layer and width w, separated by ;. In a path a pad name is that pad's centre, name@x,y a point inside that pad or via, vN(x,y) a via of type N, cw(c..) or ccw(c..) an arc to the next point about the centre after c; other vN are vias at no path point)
+IN_BIas: J7.2 R10.1 R14.2 R17.1 U1.17 | length 2390.5
  Top Layer w10: U1.17@2066.93,2564.96 2066.93,2629.51 2087.4,2649.98
  Top Layer w25: R17.1@2086.5,2207 v1(2086.5,2260.16) ; 2087.4,2649.98 v3(2087.4,2765) ; v3(2088.07,2950) 2088.07,2979.07 2287.32,3178.33 2603.83,3178.33 2882.32,3456.82 2882.32,3536 ; R14.2@2829.5,3536 2882.32,3536 ; J7.2@2882.32,3716.56 2882.32,3536 ; R10.1@2916.5,3536 2882.32,3536
  Int 3 V+ w25: v1(2086.5,2260.16) 2172.4,2346.06 2172.4,2680 v3(2087.4,2765)
  Bottom Layer w25: v3(2087.4,2765) 2088.07,2765.67 v3(2088.07,2950)
AmpB_FB: R13.1 R16.2 R17.2 U1.8 | length 293.1
  Top Layer w12: R13.1@2024.61,2325 2026.5,2326.89 2026.5,2356.5 2047.24,2377.24 U1.8@2047.24,2435.04
  Top Layer w25: R13.1@2024.61,2325 2024.61,2208.1 R17.2@2023.5,2207 2023.5,2156 2025.5,2154 R16.2@2026.5,2154.99
DGND_Sel_U1: J16.2 R24.1 R25.1 R26.1 R27.1 TP5.1 U1.3 | length 4272.1
  Top Layer w10: v4@1949.36,2512.36 1959.91,2501.81 1980.47,2501.81 U1.3@1982.28,2500
  Top Layer w25: v1(445,2085) R24.1@507.41,2085 ; v1(705,2085) R25.1@765.96,2085 ; v1(970,2085) R26.1@1024.52,2085 ; v1(1235,2084) 1236,2085 R27.1@1283.07,2085
  Top Layer w50: J16.2@432.5,3150 v2(750,3150)
  Int 3 V+ w25: v1(705,2085) 705,2486.79 750,2531.79 v2(750,3150)
  Bottom Layer w12: 1902,2494 1931,2494 v4@1943,2506
  Bottom Layer w25: v1(445,2085) 445,2015 463.91,1996.09 701.09,1996.09 ; v1@706.14,2083.86 706.14,2001.14 701.09,1996.09 ; v1(970,2085) 970,2000 966.09,1996.09 ; v1(1235,2084) 1235,1996.09 966.09,1996.09 ; 701.09,1996.09 966.09,1996.09
  Bottom Layer w50: v2(750,3150) 900,3150 1556.87,2493.13 1767.34,2493.13 1768.22,2494 1902,2494
  other v4: 1945,2506
DGND_SEL_U2: J35.2 R53.1 R54.1 R55.1 R56.1 TP21.1 U2.3 | length 4151.9
  Top Layer w10: v4(5068,2505) 5073.79,2499.21 U2.3@5105.04,2499.21
  Top Layer w25: v1(3705,2083) 3707,2085 R53.1@3769.41,2085 ; v1(3975,2085) R54.1@4027.96,2085 ; v1(4240,2085) R55.1@4286.51,2085 ; v1(4495,2084) 4496,2085 R56.1@4545.07,2085
  Top Layer w50: J35.2@3907.5,3148.23 v2(4250,3148.23)
  Int 3 V+ w25: v1(3975,2085) 4250,2360 v2(4250,3148.23)
  Bottom Layer w10: 5028.79,2499.21 5032.57,2503 v4@5072,2503
  Bottom Layer w25: v1(3705,2083) 3705,1995 3968.21,1995 ; v1(3975,2085) 3975,2001.79 3968.21,1995 ; v1(4240,2085) 4240,2005 4230,1995 ; v1(4495,2084) 4490,2079 4490,1995 4230,1995 ; 3968.21,1995 4230,1995
  Bottom Layer w50: v2(4250,3148.23) 4250,2919.21 4670,2499.21 5028.79,2499.21
GND: C2.1 C3.2 C6.2 C7.1 C8.1 C9.2 C14.2 C16.1 C17.1 C18.1 C20.2 C23.2 D1.2 D3.1 J2.1 J4.2 J4.3 J4.4 J4.5 J5.3 J6.2 J6.3 J6.4 J6.5 J7.3 J8.2 J8.3 J8.4 J8.5 J9.2 J9.3 J9.4 J9.5 J10.3 J11.3 J16.1 J17.2 J17.3 J17.4 J17.5 J18.3 J19.2 J19.3 J19.4 J19.5 J20.2 J20.3 J20.4 J20.5 J21.3 J22.2 J22.3 J22.4 J22.5 J23.3 J24.2 J24.3 J24.4 J24.5 J25.2 J25.3 J25.4 J25.5 J26.3 J27.2 J27.3 J27.4 J27.5 J28.3 J33.2 J33.3 J33.4 J33.5 J34.3 J35.1 R12.1 R16.1 R21.1 R38.1 R43.1 TP10.1 TP11.1 TP17.1 TP18.1 | length 3381.3
  Top Layer w25: v1(200,3050) J16.1@317.5,3050 ; v1(1700,2810) C6.2@1758.5,2810 ; v1(1735,2365) 1745,2375 C9.2@1805,2375 ; v1(1740,2645) 1785,2645 C7.1@1805,2625 ; R12.1@2015.09,1840.9 2089.1,1840.9 v1(2090,1840) ; C8.1@2017.29,1716.3 v1(2090,1716.3) ; R16.1@2086.5,2152 2086.5,2086.58 v1(2088.07,2085) ; v1(2184.36,2152) 2186.33,2153.97 R21.1@2186.33,2222.61 ; v1(3675,3045) 3678.23,3048.23 J35.1@3792.5,3048.23 ; v1(4800,2180) C23.2@4898.5,2180 ; v1(4830,2820) C14.2@4888.5,2820 ; v1(4840,2377) 4842,2375 C20.2@4927,2375 ; v1@4843.68,2625 4843.68,2623.68 4845,2625 C17.1@4927,2625 ; v1(6210,2800.96) R38.1@6210,2882.91 ; v1(6320,2801.46) C16.1@6320,2882.91
  Top Layer w50: J5.3@1887,3831.5 1954.5,3831.5 1955,3831 v1(1965,3831) ; J10.3@2434.5,3831.5 v1(2541.84,3831.5) v1@2542.5,3831.5 ; J7.3@2982,3831.5 v1(3137,3831.5) v1@3143.5,3831.5 ; D1.2@3143.31,4500 3166.93,4523.62 C2.1@3166.93,4720 3171.93,4725 J2.1@3500,4725 C3.2@3855.34,4725 3855.34,4519.36 D3.1@3874.69,4500 ; v1(4750,1242.5) J26.3@4838.96,1242.5 ; J11.3@4850,4760.4 4982.6,4760.4 v1(4983,4760) ; J18.3@5000,3807.5 v1(5090,3807.5) ; v1(5310,1240) 5312.5,1242.5 J28.3@5386.46,1242.5 ; J21.3@5552.93,3807.5 5649.72,3807.5 v1(5650,3807.78) ; v1@5860,1240 v1(5860,1242.5) J34.3@5933.96,1242.5 ; J23.3@6105.86,3807.78 6199.72,3807.78 v1(6200,3807.5)
  other v1: 4843.68,2633.68
  other v2: 4000,2498 475,2500.69 475,2596.58 3999.65,2600.23
  other v5: 6575,1000 3050,1432 3050,3300 6575,3550
MUXOUT: R19.1 TP6.1 U1.10 | length 861.8
  Top Layer w8: U1.10@2086.61,2435.04 2086.61,2371.64 2099.26,2359
  Top Layer w25: 2099.26,2359 2211.31,2359 v3(2215.57,2363.26)
  Bottom Layer w25: v3(2215.57,2363.26) 2329.59,2249.23 2447.33,2249.23 2650.66,2045.9 v1(2650.66,1950)
NetC1_1: C1.1 R1.1 | length 78.7
  Top Layer w25: R1.1@2385.5,2676 2386,2676.5 C1.1@2386,2754.5
NetC1_2: C1.2 C4.2 C5.2 D4.1 D5.2 R2.1 R4.1 R5.2 R7.1 R8.2 U1.18 | length 1752.5
  Top Layer w10: 2041.55,2631.47 2047.24,2625.78 U1.18@2047.24,2564.96
  Top Layer w25: R5.2@1971.5,2810 1975.5,2814 2041.55,2814 ; D4.1@1984.8,3248.03 2041.55,3191.28 2041.55,2814 ; 2041.55,2631.47 2041.55,2814 ; R4.1@2660,2817.5 C4.2@2590,2817.5 R2.1@2451,2817.5 C1.2@2386,2817.5 R7.1@2245,2817.5 C5.2@2180,2817.5 2176.5,2814 2041.55,2814
  Top Layer w50: R8.2@1785.08,3250 D4.1@1985.01,3250 ; D4.1@1984.8,3248.03 1985.01,3248.24 D4.1@1985.01,3250 ; D5.2@1985.01,3400 D4.1@1985.01,3250
NetC4_1: C4.1 R3.1 | length 79.5
  Top Layer w25: C4.1@2590,2754.5 2590,2678.5 R3.1@2592.5,2676
NetC5_1: C5.1 R6.1 | length 78.7
  Top Layer w25: R6.1@2179.5,2676 2180,2676.5 C5.1@2180,2754.5
NetC6_1: C6.1 R5.1 | length 87
  Top Layer w25: C6.1@1821.5,2810 R5.1@1908.5,2810
NetC8_2: C8.2 J8.1 R11.2 R12.2 | length 515.9
  Top Layer w50: J8.1@1903.41,1432 R11.2@1903.41,1947.91
NetC12_1: C12.1 R28.1 | length 78.7
  Top Layer w25: C12.1@5730,2754.5 5730,2676.5 R28.1@5730.5,2676
NetC12_2: C12.2 C13.2 C15.2 D6.1 D7.2 R29.2 R30.1 R32.2 R33.1 R37.1 U2.18 | length 1774.3
  Top Layer w10: 5161.14,2613.79 5170,2604.93 U2.18@5170,2564.17
  Top Layer w25: R32.2@5091.5,2820 5093.5,2818 5161.14,2818 ; D6.1@5116.33,3247.96 5161.14,3203.15 5161.14,2818 ; 5161.14,2613.79 5161.14,2818 ; R30.1@5795,2817.5 R33.1@5590,2817.5 R37.1@5385,2817.5 5161.65,2817.5 5161.14,2818
  Top Layer w50: R29.2@4905.79,3247.96 5116.33,3247.96 5119.01,3250.64 D7.2@5119.01,3400
NetC13_1: C13.1 R31.1 | length 79.1
  Top Layer w25: C13.1@5525,2754.5 5525,2677.5 R31.1@5526.5,2676
NetC14_1: C14.1 R32.1 | length 77
  Top Layer w25: C14.1@4951.5,2820 R32.1@5028.5,2820
NetC16_2: C16.2 J20.1 R36.2 R38.2 TP19.1 | length 809.8
  Top Layer w50: R36.2@6093,3000.09 6093.91,3001 6576,3001 J20.1@6575,3000 TP19.1@6575,2675
NetC18_2: C18.2 J24.1 R42.2 R43.2 TP20.1 | length 811.4
  Top Layer w50: R42.2@6086,1710.98 R43.2@6208.03,1710.98 6273.34,1710.98 6274.36,1712 J24.1@6572,1712 ; TP20.1@6575,1387 J24.1@6575,1712
NetC22_2: C22.2 C24.2 C25.2 C26.2 D8.1 D9.2 R45.2 R48.2 R49.1 R52.1 R59.1 R61.1 U2.8 | length 1954.2
  Top Layer w10: 5161.91,2379.25 5162.1,2379.44 5162.1,2399.81 5170,2407.71 U2.8@5170,2434.25
  Top Layer w25: R48.2@5111.5,2180 5114,2182.5 5161.91,2182.5 ; D8.1@5118.73,1725 5118.73,2075 5161.91,2118.18 5161.91,2182.5 ; 5161.91,2379.25 5161.91,2182.5 ; R61.1@6000,2182.5 C25.2@5730,2182.5 C24.2@5525,2182.5 C22.2@5322,2182.5 5161.91,2182.5
  Top Layer w50: R45.2@4938.96,1714.28 4949.67,1725 D8.1@5118.73,1725 ; D9.2@5119.01,1575 D8.1@5119.01,1725
NetC23_1: C23.1 R48.1 | length 87
  Top Layer w25: C23.1@4961.5,2180 R48.1@5048.5,2180
NetC24_1: C24.1 R51.1 | length 79.1
  Top Layer w25: C24.1@5525,2245.5 5525,2322.5 R51.1@5526.5,2324
NetC25_1: C25.1 R58.1 | length 79.1
  Top Layer w25: R58.1@5728.5,2324 5730,2322.5 C25.1@5730,2245.5
NetC26_1: C26.1 R60.1 | length 78.7
  Top Layer w25: C26.1@5935,2245.5 5935,2323.5 R60.1@5935.5,2324
NetD4_2: D4.2 D5.1 J10.2 R15.1 R18.2 | length 762.9
  Top Layer w25: D5.1@2110.99,3400 2273,3400 2334.5,3461.5 2334.5,3535 ; R18.2@2278.99,3536 2279.99,3535 2334.5,3535 ; J10.2@2334.5,3716.5 2334.5,3535 ; R15.1@2385,3536 2384,3535 2334.5,3535
  Top Layer w50: D4.2@2110.79,3248.03 2110.99,3248.24 D5.1@2110.99,3400
NetD6_2: D6.2 D7.1 J21.2 R35.1 R39.2 | length 614.1
  Top Layer w25: D7.1@5244.99,3400 5302.93,3400 5452.93,3550 ; 5452.93,3607.94 5452.93,3550 ; R35.1@5488.5,3536 5452.93,3536 5452.93,3550
  Top Layer w50: D6.2@5244.99,3248 D7.1@5244.99,3400 ; 5452.93,3607.94 J21.2@5452.93,3692.5
NetD8_2: D8.2 D9.1 J28.2 R46.1 R47.2 | length 703.9
  Top Layer w25: D9.1@5244.99,1575 5455.11,1575 5486.46,1543.65 5486.46,1480.14 ; R46.1@5437.99,1487.74 5478.85,1487.74 5486.46,1480.14 ; J28.2@5486.46,1357.5 5486.46,1480.14 ; R47.2@5544.96,1487.74 5494.06,1487.74 5486.46,1480.14
  Top Layer w50: D9.1@5244.99,1575 D8.2@5244.99,1725
NetJ4_1: J4.1 J5.1 | length 317.8
  Top Layer w50: J5.1@1687.28,3831.56 1688.07,3832.34 J4.1@1688.07,4149.06
NetJ5_2: J5.2 R8.1 | length 353.3
  Top Layer w50: R8.1@1785.08,3364.17 1785.08,3714.35 J5.2@1787.28,3716.56
NetJ6_1: J6.1 J7.1 | length 317.8
  Top Layer w50: J7.1@2782.32,3831.56 2783.07,3832.3 J6.1@2783.07,4149.06
NetJ9_1: J9.1 J10.1 | length 318.9
  Top Layer w50: J10.1@2234.5,3831.5 2235.5,3832.5 J9.1@2235.5,4150
NetJ16_3: J16.3 TP12.1 | length 304.2
  Top Layer w50: J16.3@317.5,3250 317.5,3539.74 TP12.1@327.76,3550
NetJ17_1: J17.1 J18.1 | length 322.3
  Top Layer w50: J18.1@4800,3807.5 4805,3812.5 J17.1@4805,4125 ; J18.1@4803.86,3807.78 J18.1@4805.79,3809.7
NetJ18_2: J18.2 R29.1 | length 334.2
  Top Layer w50: R29.1@4903.86,3364.07 4905.79,3362.14 4905.79,3690.85 J18.2@4903.86,3692.78
NetJ19_1: J19.1 J21.1 | length 317.7
  Top Layer w50: J19.1@5352.5,4125 5352.5,3807.93 J21.1@5352.93,3807.5
NetJ22_1: J22.1 J23.1 | length 318.7
  Top Layer w50: J22.1@5902.85,4125.28 5902.85,3810.78 J23.1@5905.86,3807.78
NetJ23_2: J23.2 R40.1 R44.2 U2.17 | length 1729.9
  Top Layer w10: U2.17@5189.69,2564.17 5189.69,2601.06 5208.94,2620.32
  Top Layer w25: 5208,2625 v3@5208,2768.74 ; v1(5208.94,2889.22) 5329.72,3010 5622,3010 5840,3228 5840,3340 6005.86,3505.86 6005.86,3530 ; R44.2@5960.5,3536 5999.86,3536 6005.86,3530 ; J23.2@6005.86,3692.78 6005.86,3542 ; R40.1@6047.5,3536 6011.86,3536 6005.86,3542 ; 6005.86,3530 6005.86,3542
  Bottom Layer w25: v3(5208.94,2764.06) v1(5208.94,2889.22)
NetJ25_1: J25.1 J26.1 | length 317.5
  Top Layer w50: J25.1@5038.96,925 J26.1@5038.96,1242.5
NetJ26_2: J26.2 R45.1 | length 242.6
  Top Layer w50: J26.2@4938.96,1357.5 R45.1@4938.96,1600.11
NetJ27_1: J27.1 J28.1 | length 317.9
  Top Layer w50: J28.1@5586.46,1242.5 5587.5,1241.46 J27.1@5587.5,925
NetJ33_1: J33.1 J34.1 | length 317.5
  Top Layer w50: J33.1@6133.96,925 J34.1@6133.96,1242.5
